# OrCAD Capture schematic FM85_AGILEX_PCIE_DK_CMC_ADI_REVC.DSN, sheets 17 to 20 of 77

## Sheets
17 FPGA BANK 2C: size B
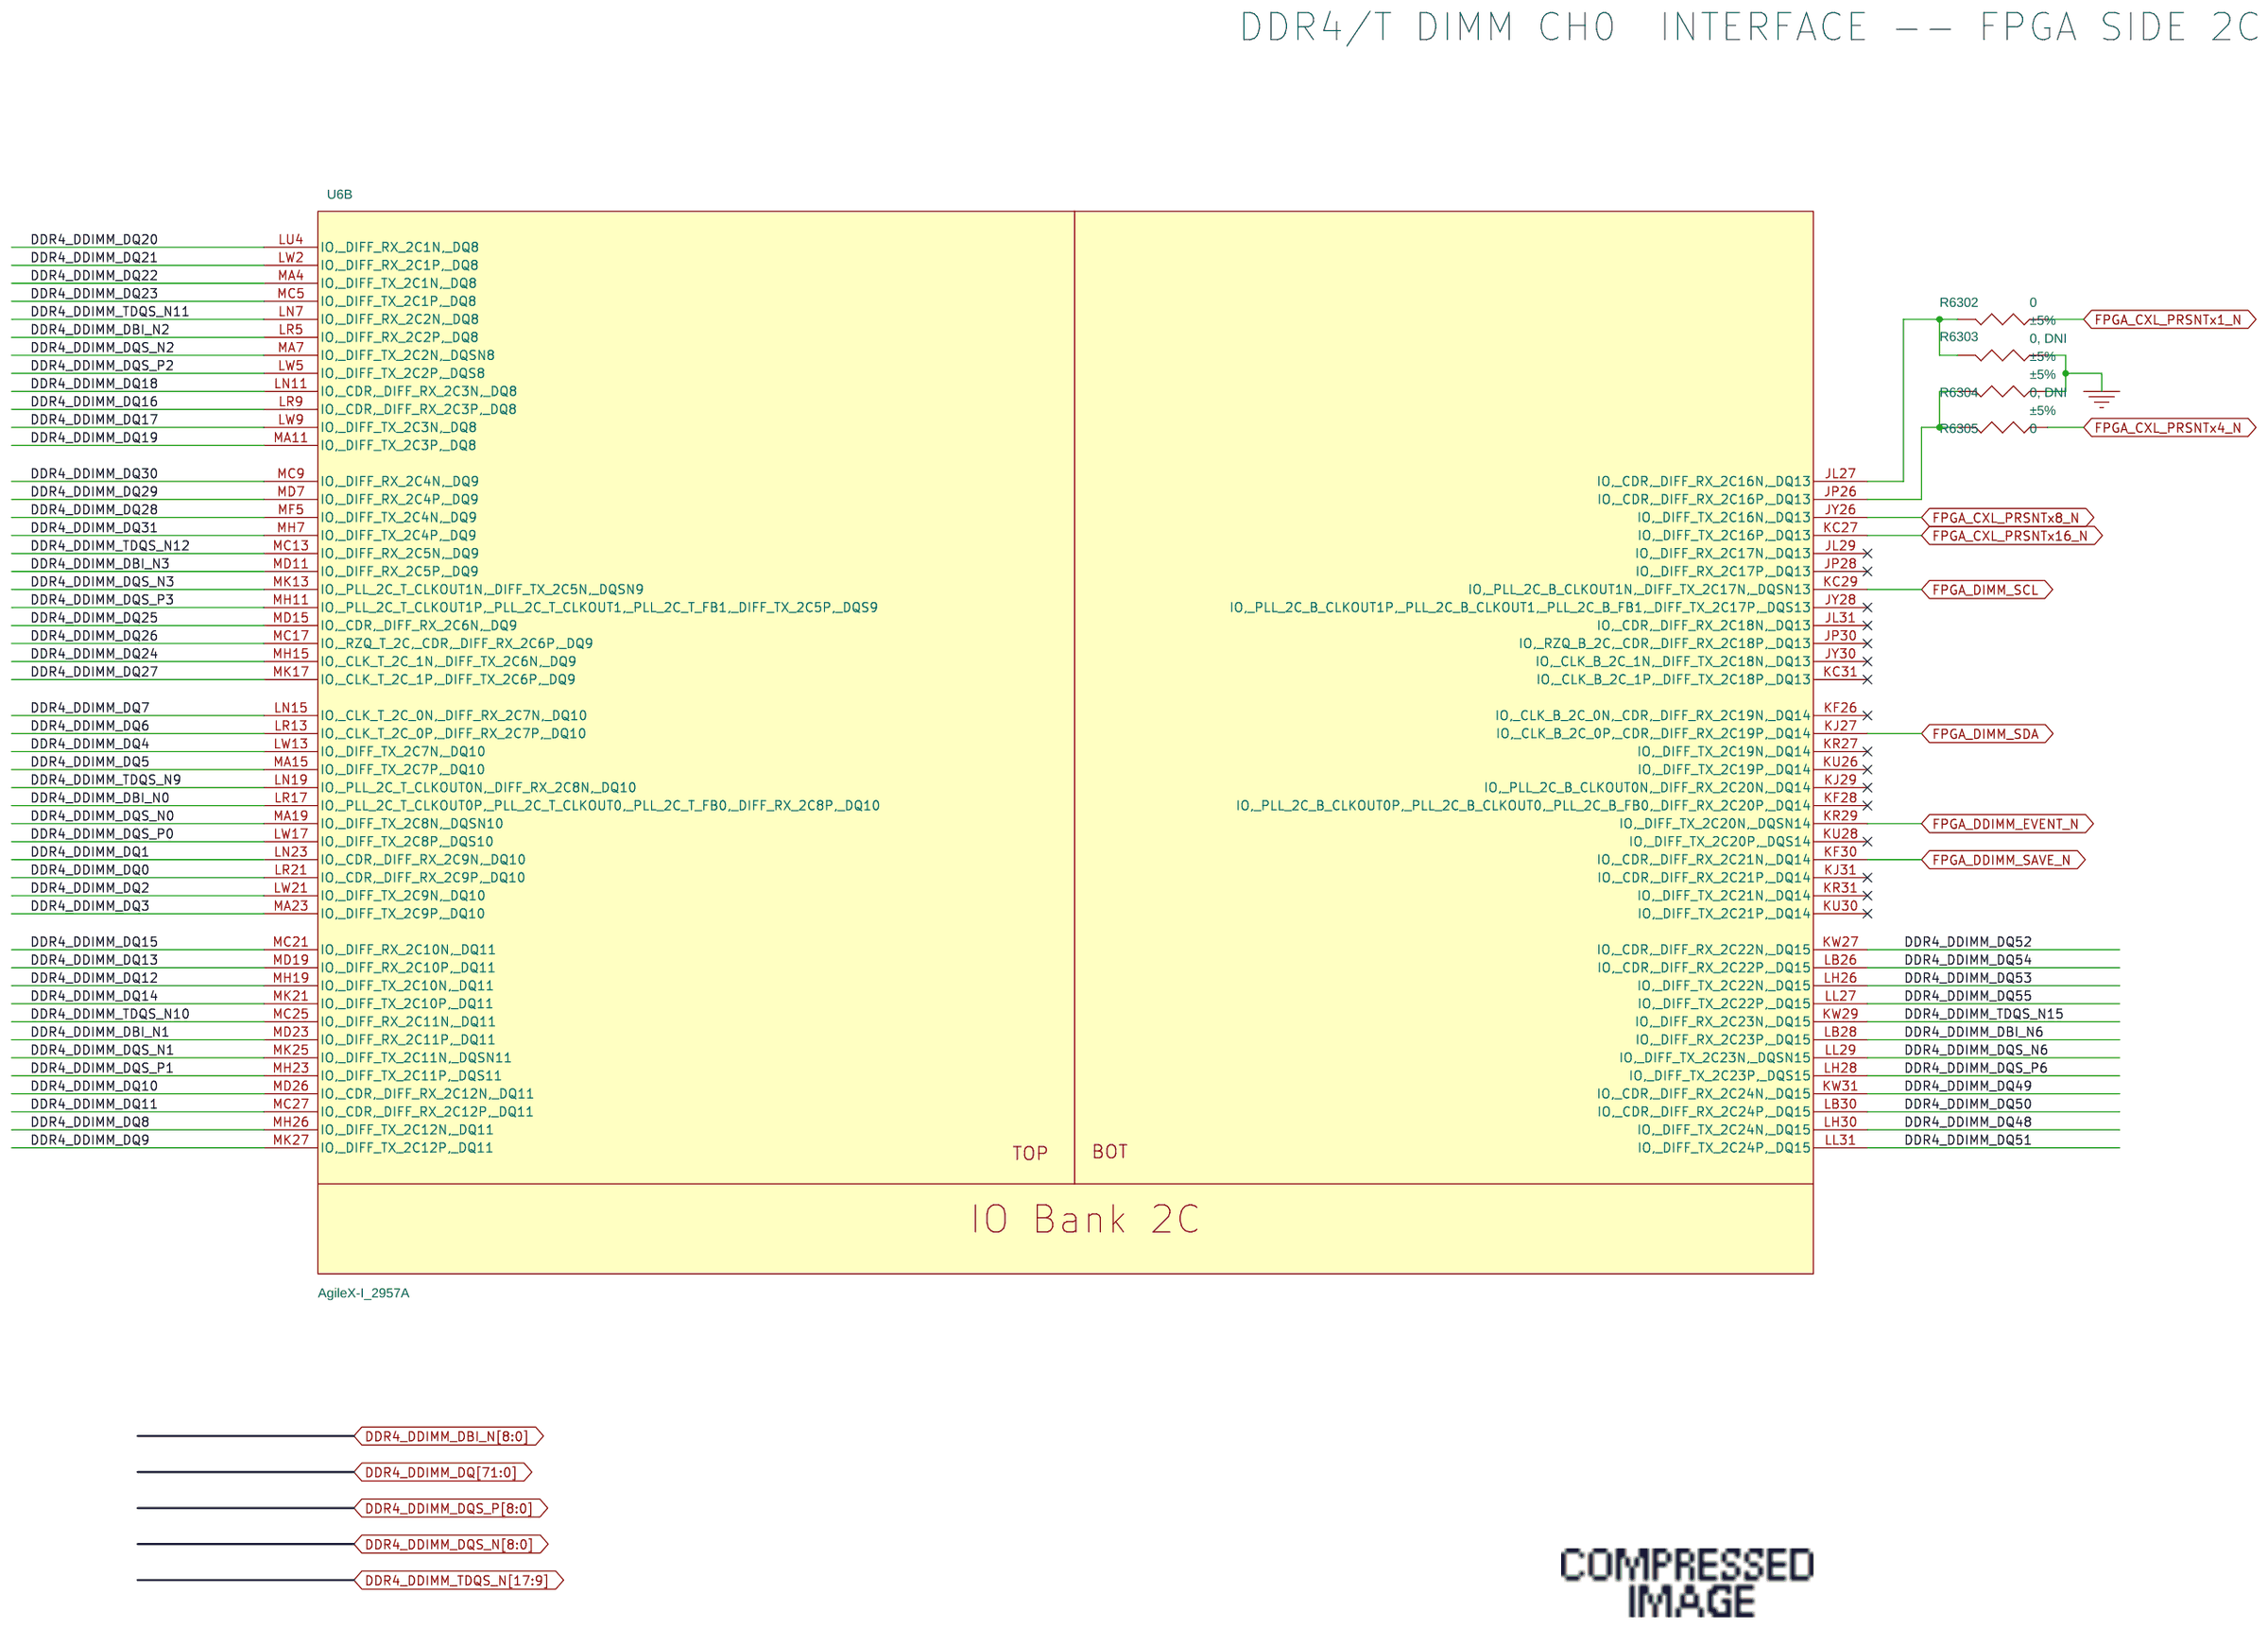
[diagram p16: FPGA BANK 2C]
18 FPGA BANK 2F: size B
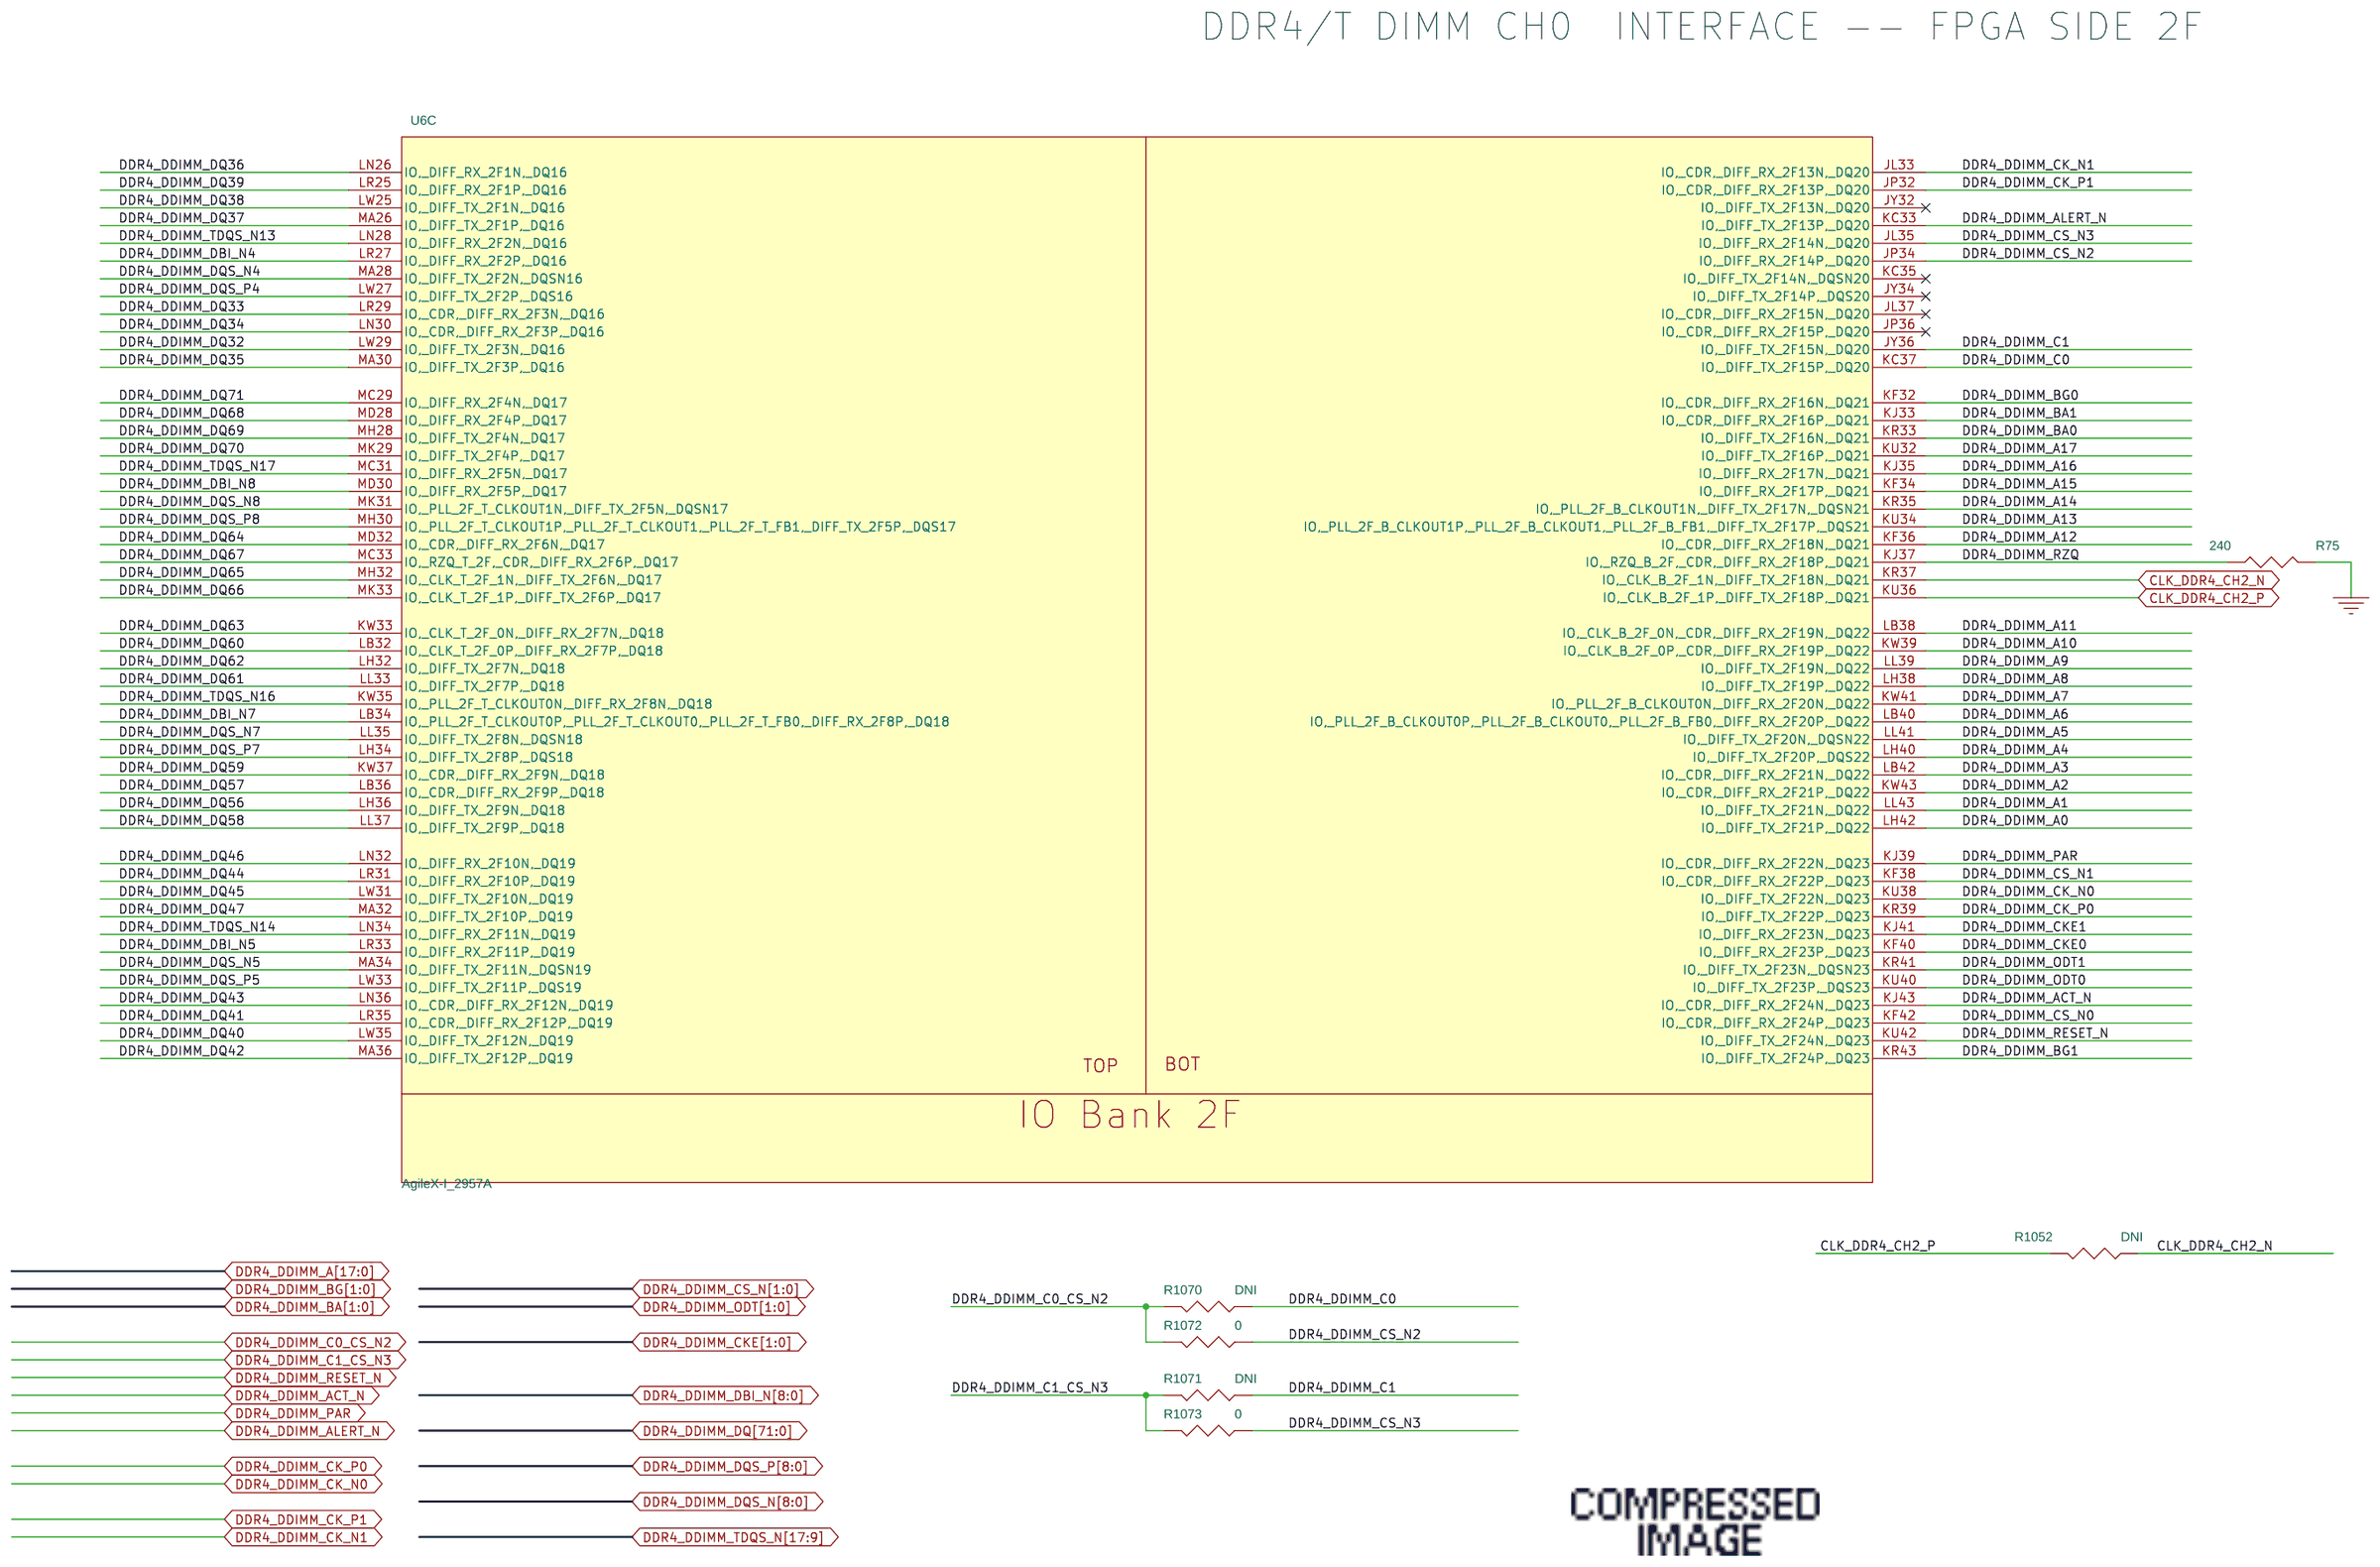
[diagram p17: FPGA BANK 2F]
19 DDR4/DDRT DIMM2: size B
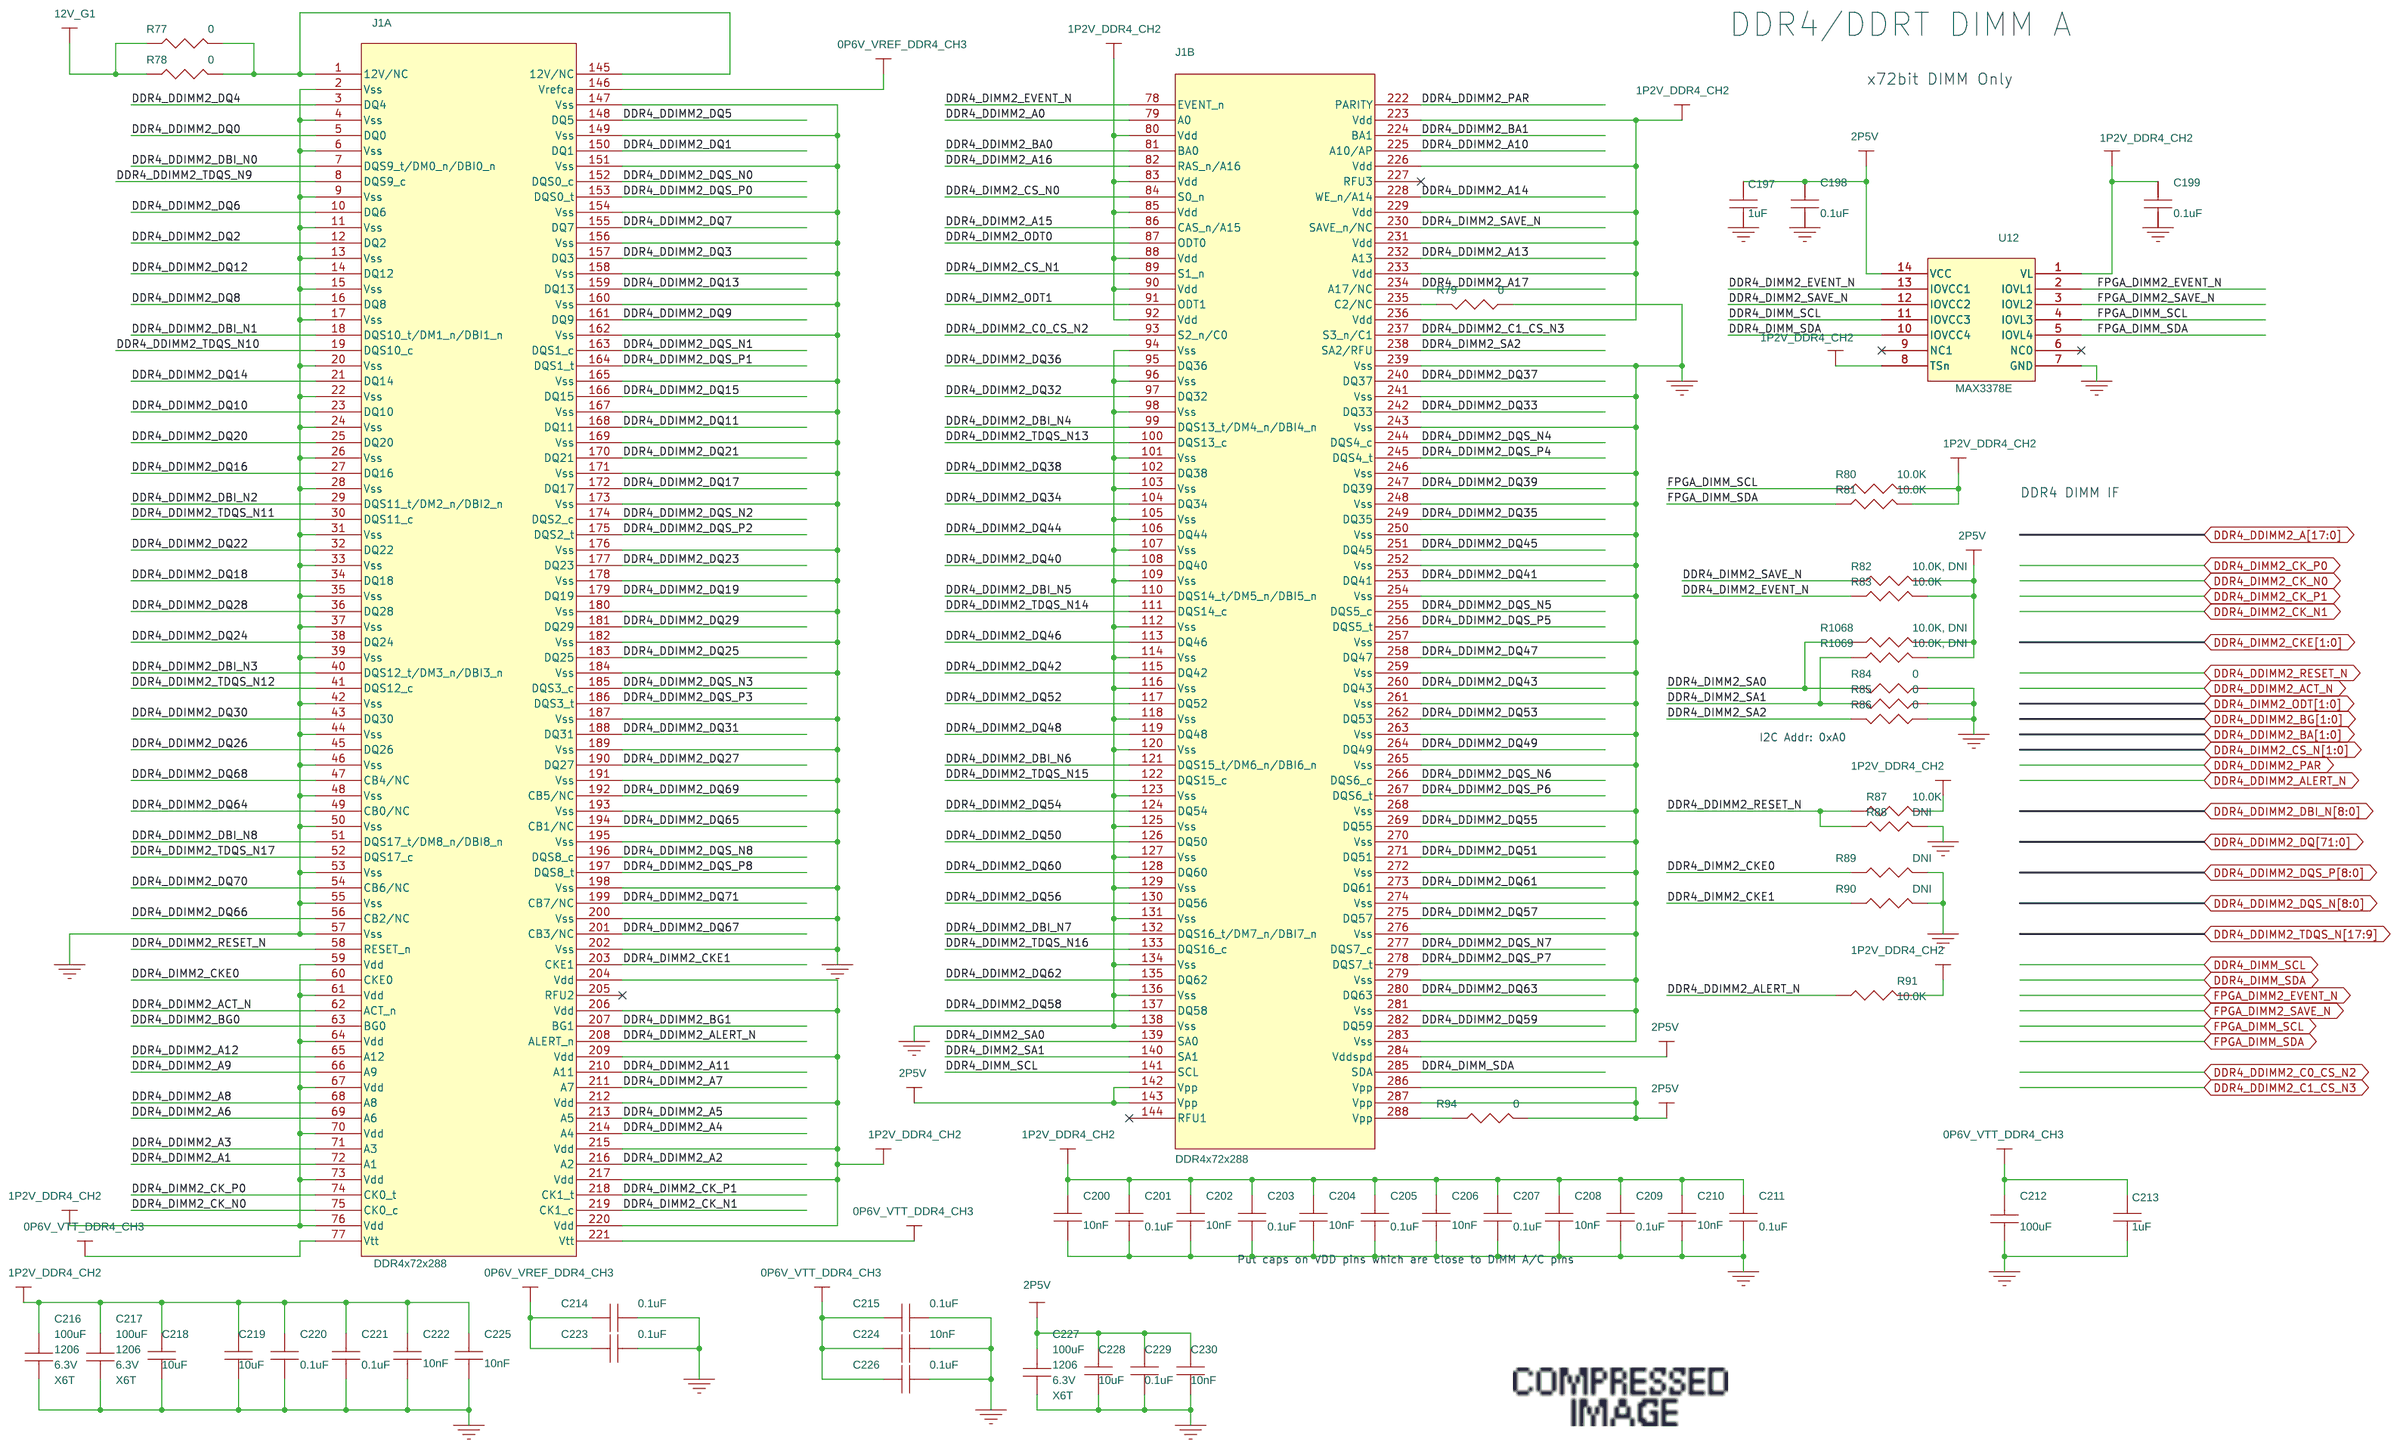
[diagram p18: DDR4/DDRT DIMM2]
20 DDR4/DDRT DIMM: size B
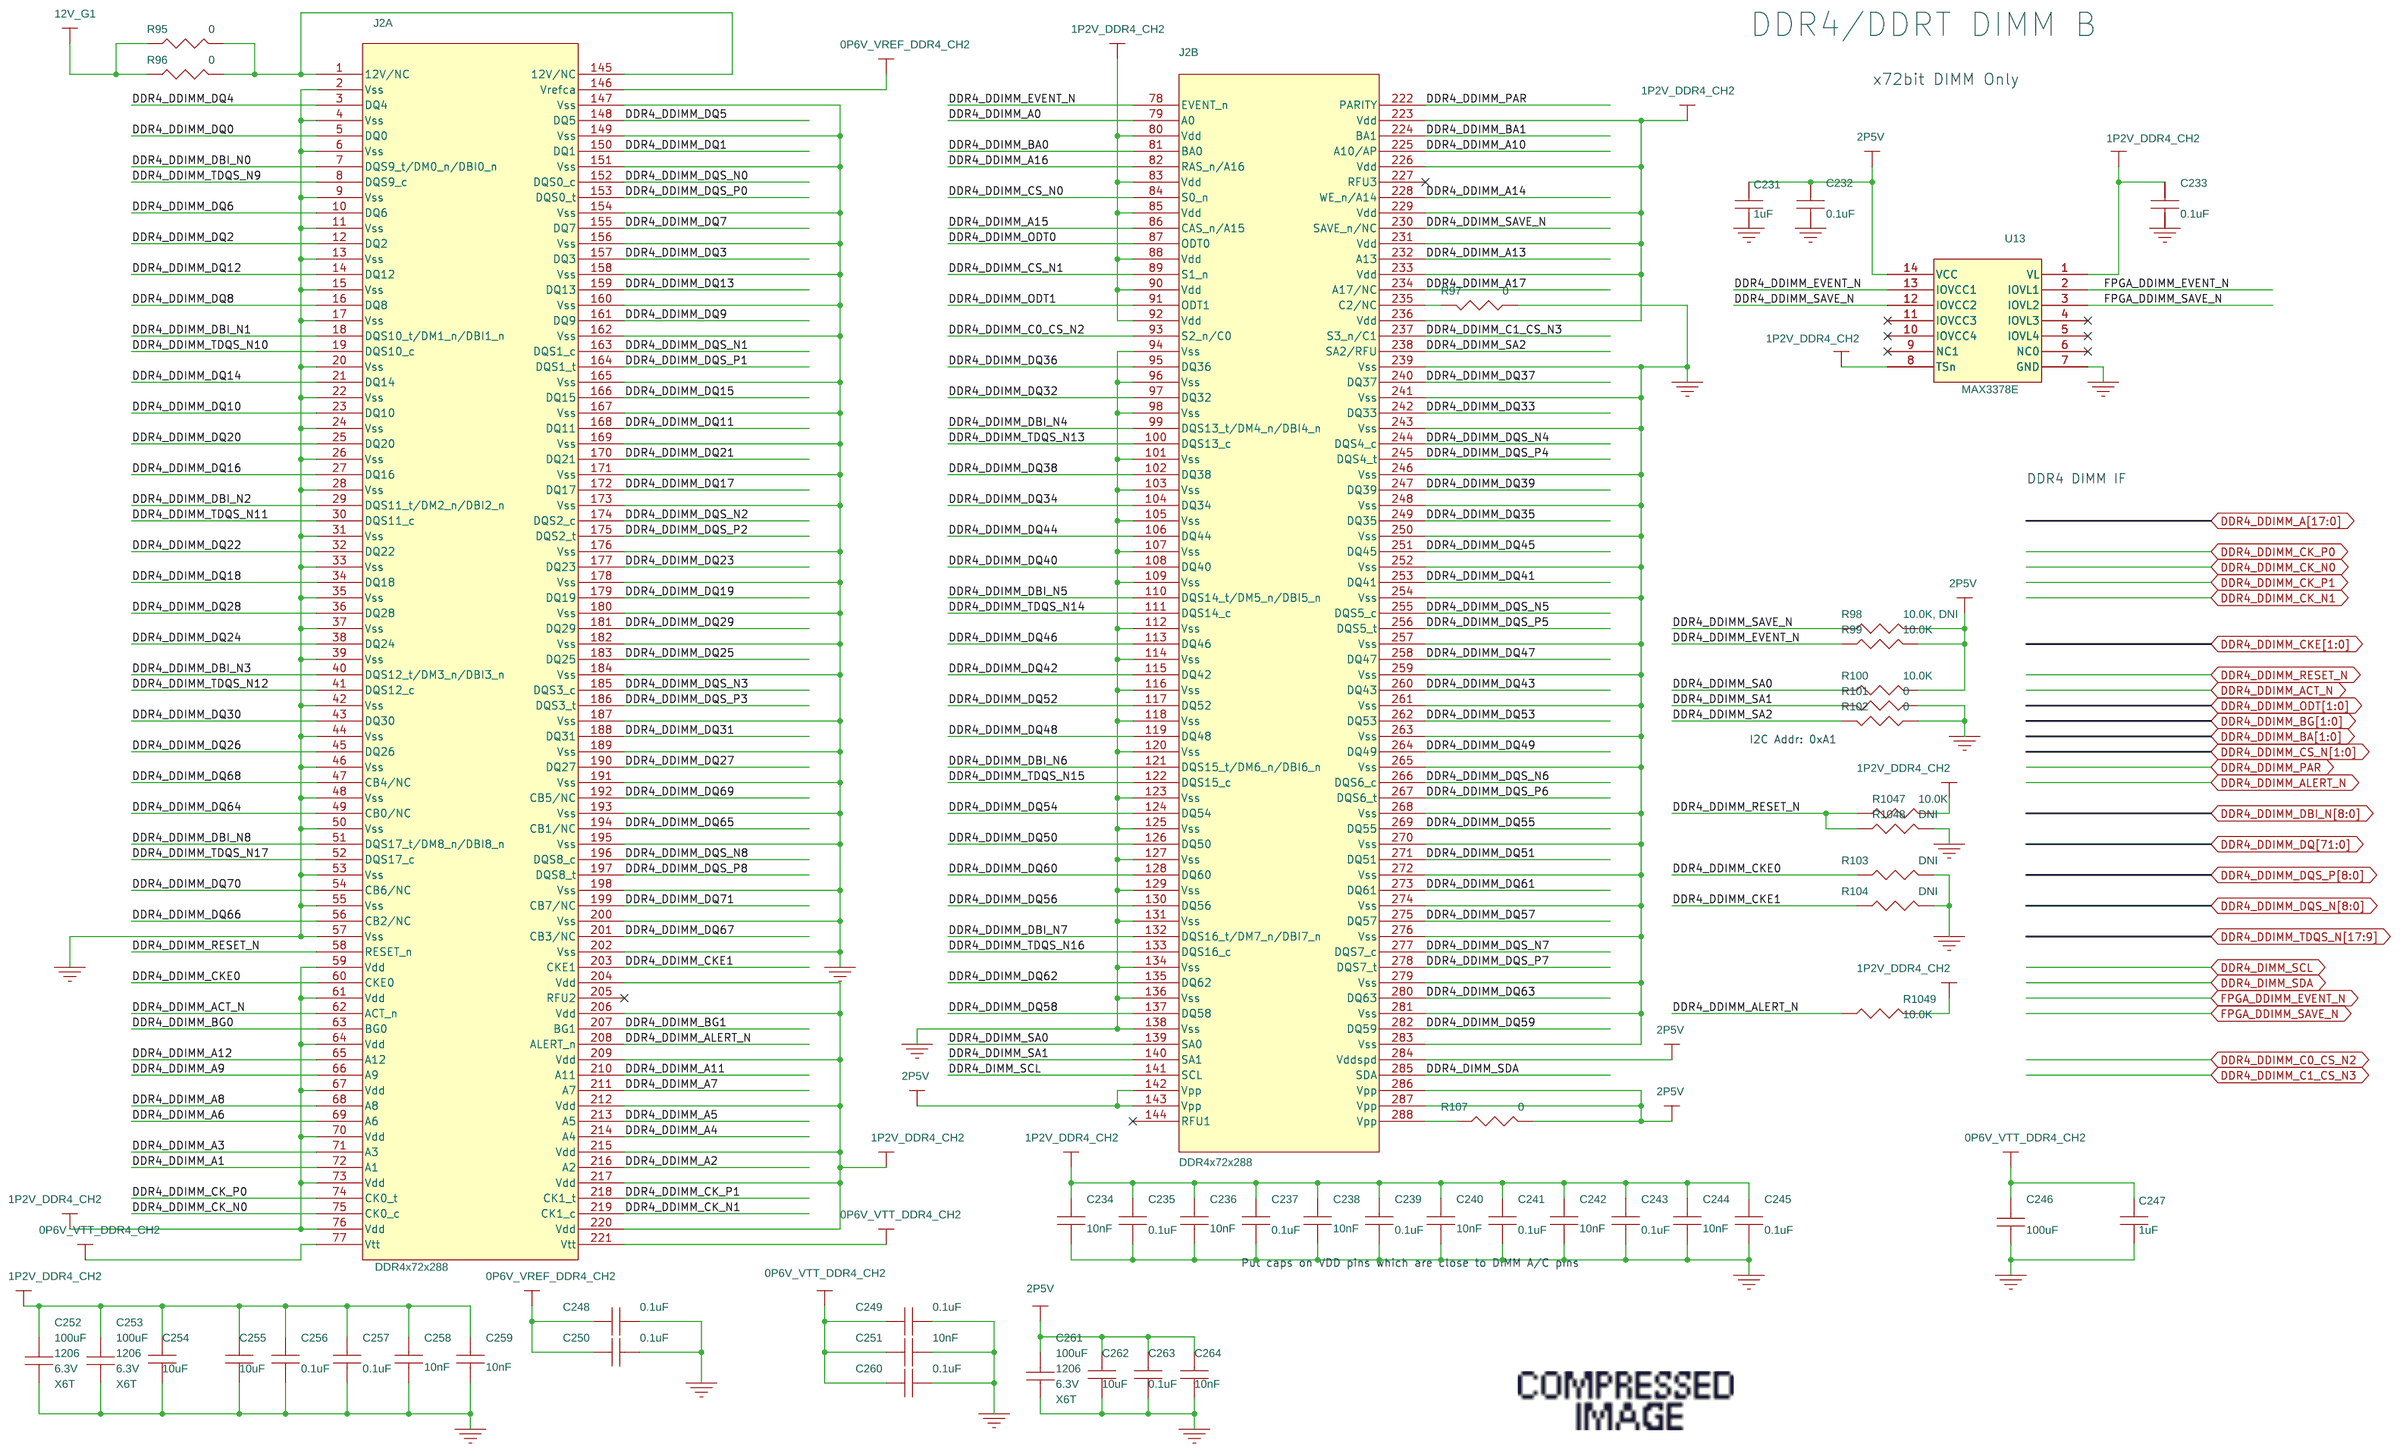
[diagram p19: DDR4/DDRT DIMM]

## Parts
sheet DDR4/DDRT DIMM2
C197  1uF  [0402]
C198  0.1uF  [0402]
C199  0.1uF  [0402]
C200  10nF  [0402]
C201  0.1uF  [0402]
C202  10nF  [0402]
C203  0.1uF  [0402]
C204  10nF  [0402]
C205  0.1uF  [0402]
C206  10nF  [0402]
C207  0.1uF  [0402]
C208  10nF  [0402]
C209  0.1uF  [0402]
C210  10nF  [0402]
C211  0.1uF  [0402]
C212  100uF  [1206]
C213  1uF  [0402]
C214  0.1uF  [0402]
C215  0.1uF  [0402]
C216  100uF  [1206]
C217  100uF  [1206]
C218  10uF  [1210]
C219  10uF  [1210]
C220  0.1uF  [0402]
C221  0.1uF  [0402]
C222  10nF  [0402]
C223  0.1uF  [0402]
C224  10nF  [0402]
C225  10nF  [0402]
C226  0.1uF  [0402]
C227  100uF  [1206]
C228  10uF  [1210]
C229  0.1uF  [0402]
C230  10nF  [0402]
J1  DDR4x72x288  [DDR4DIMM_SMT]  (sections A,B)
R77  0  [1206]
R78  0  [1206]
R79  0  [0402]
R80  10.0K  [0402]
R81  10.0K  [0402]
R82  10.0K, DNI  [0402]
R83  10.0K  [0402]
R84  0  [0402]
R85  0  [0402]
R86  0  [0402]
R87  10.0K  [0402]
R88  DNI  [0402]
R89  DNI  [0402]
R90  DNI  [0402]
R91  10.0K  [0402]
R94  0  [0603]
R1068  10.0K, DNI  [0402]
R1069  10.0K, DNI  [0402]
U12  MAX3378E  [TSSOP-14]
sheet DDR4/DDRT DIMM
C231  1uF  [0402]
C232  0.1uF  [0402]
C233  0.1uF  [0402]
C234  10nF  [0402]
C235  0.1uF  [0402]
C236  10nF  [0402]
C237  0.1uF  [0402]
C238  10nF  [0402]
C239  0.1uF  [0402]
C240  10nF  [0402]
C241  0.1uF  [0402]
C242  10nF  [0402]
C243  0.1uF  [0402]
C244  10nF  [0402]
C245  0.1uF  [0402]
C246  100uF  [1206]
C247  1uF  [0402]
C248  0.1uF  [0402]
C249  0.1uF  [0402]
C250  0.1uF  [0402]
C251  10nF  [0402]
C252  100uF  [1206]
C253  100uF  [1206]
C254  10uF  [1210]
C255  10uF  [1210]
C256  0.1uF  [0402]
C257  0.1uF  [0402]
C258  10nF  [0402]
C259  10nF  [0402]
C260  0.1uF  [0402]
C261  100uF  [1206]
C262  10uF  [1210]
C263  0.1uF  [0402]
C264  10nF  [0402]
J2  DDR4x72x288  [DDR4DIMM_SMT]  (sections A,B)
R95  0  [1206]
R96  0  [1206]
R97  0  [0402]
R98  10.0K, DNI  [0402]
R99  10.0K  [0402]
R100  10.0K  [0402]
R101  0  [0402]
R102  0  [0402]
R103  DNI  [0402]
R104  DNI  [0402]
R107  0  [0603]
R1047  10.0K  [0402]
R1048  DNI  [0402]
R1049  10.0K  [0402]
U13  MAX3378E  [TSSOP-14]
sheet FPGA BANK 2C
R6302  0  [0402]
R6303  0, DNI  [0402]
R6304  0, DNI  [0402]
R6305  0  [0402]
sheet FPGA BANK 2F
R75  240  [0402]
R1052  DNI  [0402]
R1070  DNI  [0402]
R1071  DNI  [0402]
R1072  0  [0402]
R1073  0  [0402]
U6  AgileX-I_2957A  [fbga2957a_hex_p56x45]  (sections A,B,C,D,E,F,G,H,I,J,K,L,M,N,O,P,Q,R,S,T,U,V,W,X,Y,Z)

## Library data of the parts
C197 C213 C231 C247 = CAP: CAP - CER, 1uF, 10V, +/-10%, X5R, 0402; Item Num: G61001-001; Lead Free Status: Yes; Manufacturer: Murata; Manufacturer Part Num: GRM155R61A105KE15D; Num Pins: 2; Part Class: CAPACITORS; RoHS Compliant: Yes
C198 C199 C201 C203 C205 C207 C211 C214 C215 C220 C221 C223 C226 C229 C232 C233 C241 C245 C248-C250 C256 C257 C263 = CAP: CAPC,  X7R, 0402, 0.1uF, 25V, ±20%; Item Num: K13660-001; LIFECYCLE_PHASE: Active; Lead Free Status: Lead Free; MFR_LIFECYCLE: Active; Manufacturer: Murata; Manufacturer Part Num: GRM155R71E104KE14D; Num Pins: 2; PART_SUBCLASS: CAPACITORS; Part Class: CAPACITORS; RATED_VOLTAGE: 25V; RoHS Compliant: RoHS Compliant; Tolerance: +80%/-20%
C200 C202 C204 C206 C208 C210 C222 C224 C225 C230 C234 C236 C238 C240 C242 C244 C251 C258 C259 C264 = Cap_10000PF_50V_0402: CAP - CERAMIC, 10nF, 0402, 50V, Y5V; Item Num: K30697-001; Manufacturer Part Num: GRM155F51H103Z
C209 C243 = CAP: CAPC,  X7R, 0402, 0.1uF, 25V, ±20%; Dielectric: Y5V; Item Num: K13660-001; LIFECYCLE_PHASE: Active; Lead Free Status: Lead Free; MFR_LIFECYCLE: Active; Manufacturer: Murata; Manufacturer Part Num: GRM155R71E104KE14D; Num Pins: 2; PART_SUBCLASS: CAPACITORS; Part Class: CAPACITORS; RATED_VOLTAGE: 25V; RoHS Compliant: RoHS Compliant; Tolerance: +80%/-20%
C212 C216 C217 C227 C246 C252 C253 C261 = CAP: CAP CER 100UF 6.3V X6T 1206; AGILE_LINK: http://sj-agile9app/Agile/PLMServlet?action=OpenEmailObject&classid=10000&objid=257560276; Item Num: H65271-004; LIFECYCLE_PHASE: Active; Lead Free Status: Lead Free; MFR_LIFECYCLE: Active; Manufacturer: Murata; Manufacturer Part Num: GRM31CD80J107ME39L; Num Pins: 2; PART_SUBCLASS: CAPACITORS; RATED_VOLTAGE: 6.3V; RoHS Compliant: RoHS Compliant; TOLERANCE: 20%; Temperature Coefficient: X6T
C218 = CAP_10uF_+_-10%_25V_1210: CAP - CER, 10UF, 25V, 10%, X5R, 1210; Agile Part Description: CAP - CER, 10UF, 25V, 10%, X5R, 1210; Item Num: G19458-001; Manufacturer Part Num: GRM32DR61E106KA12L
C219 C254 C255 = CAP_10uF_+_-10%_25V_1210: CAP - CER, 10UF, 25V, 10%, X5R, 1210; Agile Part Description: CAP - CER, 10UF, 25V, 10%, X7R, 1210; Item Num: G19458-001; Manufacturer Part Num: GRM32DR61E106KA12L
C228 C262 = CAP_10uF_+_-10%_25V_1210: CAP - CER, 10UF, 25V, 10%, X7R, 1210; Agile Part Description: CAP - CER, 10UF, 25V, 10%, X5R, 1210; Item Num: G19458-001; Manufacturer Part Num: GRM32DR61E106KA12L
J1 J2 = DDR4x72x288_1: CONN SMT DDR4 288POS VERT; COMPGROUP: DDR4_PINGPONG_DIMMA; Item Num: K21528-001; Manufacturer: Molex Inc; Manufacturer Part Num: 787301002
R77 R78 R95 R96 = RESISTOR: RES SMD 0 OHM JUMPER 3/4W 1206; AGILE_LINK: http://sj-agile9app/Agile/PLMServlet?action=OpenEmailObject&classid=10000&objid=146548997; Item Num: A93552-015; LIFECYCLE_PHASE: Active; Lead Free Status: No; MFR_LIFECYCLE: Active; Manufacturer: Vishay Dale; Manufacturer Part Num: CRCW12060000Z0EAHP; Num Pins: 2; PART_SUBCLASS: RESISTORS; POWER: 3/4W; RoHS Compliant: Yes; TOLERANCE: +/-1%
R79 R84-R86 R97 R101 R102 R1070-R1073 = RES_0_OHM_5%_1_16W_0402_SMD: Item Num: H30887-001
R80 R81 R83 R87 R91 R99 R100 R1047 R1049 = RESISTOR: RES,10.0K OHMS,1.0%,1/16W, 0402; AGILE_LINK: http://sj-agile9app/Agile/PLMServlet?action=OpenEmailObject&classid=10000&objid=146548997; Item Num: K28115-001; LIFECYCLE_PHASE: Active; Lead Free Status: No; MFR_LIFECYCLE: Active; Manufacturer: Panasonic; Manufacturer Part Num: ERJ-2RKF1002X; Num Pins: 2; PART_SUBCLASS: RESISTORS; POWER: 1/16W; RoHS Compliant: Yes; TOLERANCE: +/-1%
R82 R98 R1068 R1069 = RESISTOR: RES,10.0K OHMS,1.0%,1/16W, 0402; AGILE_LINK: http://sj-agile9app/Agile/PLMServlet?action=OpenEmailObject&classid=10000&objid=146548997; Item Num: K28115-001; LIFECYCLE_PHASE: Active; Lead Free Status: No; MFR_LIFECYCLE: Active; Manufacturer: Panasonic; Manufacturer Part Num: ERJ-2RKF1002X; Num Pins: 2; PART_SUBCLASS: RESISTORS; POWER: 1/16W; RESISTANCE: 10.0K; RoHS Compliant: Yes; TOLERANCE: +/-1%
R88-R90 R103 R104 R1048 = RESISTOR: RES ZERO OHM 1/16W 5% 0402 SMD; Item Num: H30887-001; Lead Free Status: No; Manufacturer: Panasonic; Manufacturer Part Num: ERJ-2GE0R00X; Num Pins: 2; Part Class: RESISTORS; Price: 0; RoHS Compliant: Yes; Tolerance: 5%
R94 R107 = RESISTOR: RES - 0 OHM, 5% 0603 1/10W; Item Num: E57868-001; Lead Free Status: No; Manufacturer: Panasonic; Manufacturer Part Num: ERJ-3GEY0R00V; Num Pins: 2; Part Class: RESISTORS; RoHS Compliant: Yes; Tolerance: 5%
U12 U13 = MAX3378E_0: IC - QUAD LOW-VOLTAGE LEVEL TRANSLATOR, +/- 15KV, ESD-PROTECTED, 1UA, 16MBPS; Item Num: C34337-001; Manufacturer: Maxim; Manufacturer Part Num: MAX3378EEUD
C235 = CAP: CAPC,  X7R, 0402, 0.1uF, 25V, ±20%; Dielectric: X7R; Item Num: K13660-001; LIFECYCLE_PHASE: Active; Lead Free Status: Lead Free; MFR_LIFECYCLE: Active; Manufacturer: Murata; Manufacturer Part Num: GRM155R71E104KE14D; Num Pins: 2; PART_SUBCLASS: CAPACITORS; Part Class: CAPACITORS; RATED_VOLTAGE: 25V; RoHS Compliant: RoHS Compliant; Tolerance: +80%/-20%
C237 C260 = CAP: CAPC,  X7R, 0402, 0.1uF, 25V, ±20%; Item Num: K13660-001; LIFECYCLE_PHASE: Active; Lead Free Status: Lead Free; MFR_LIFECYCLE: Active; Manufacturer: Murata; Manufacturer Part Num: GRM155F51E104ZA01D; Num Pins: 2; PART_SUBCLASS: CAPACITORS; Part Class: CAPACITORS; RATED_VOLTAGE: 25V; RoHS Compliant: RoHS Compliant; Tolerance: +80%/-20%
C239 = CAP: CAP - CERAMIC,  0.1UF 0402 25VDC X7R; Dielectric: Y5V; Item Num: K13560-001; LIFECYCLE_PHASE: Active; Lead Free Status: Lead Free; MFR_LIFECYCLE: Active; Manufacturer: Murata; Manufacturer Part Num: GRM155R71E104KE14D; Num Pins: 2; PART_SUBCLASS: CAPACITORS; Part Class: CAPACITORS; RATED_VOLTAGE: 25V; RoHS Compliant: RoHS Compliant; Tolerance: +80%/-20%
R6302 R6305 = RESISTOR: RES ZERO OHM 1/16W 5% 0402 SMD; Agile IPN: P02-14020R; Altera Part No.: P02-14020R; Item Num: H30887-001; Lead Free Status: No; Manufacturer: Panasonic; Manufacturer Part Num: ERJ-2GE0R00X; Num Pins: 2; Part Class: RESISTORS; RoHS Compliant: Yes; Tolerance: ±5%
R6303 R6304 = RESISTOR: RES ZERO OHM 1/16W 5% 0402 SMD; Agile IPN: P02-14020R; Altera Part No.: P02-14020R; Item Num: H30887-001; Lead Free Status: No; Manufacturer: Panasonic; Manufacturer Part Num: ERJ-2GE0R00X; Num Pins: 2; Part Class: RESISTORS; Price: 0; RoHS Compliant: Yes; Tolerance: ±5%
R75 = RESISTOR: RES - 240 OHM, 1/16W, 1%, 0402 SMD; Item Num: K15783-001; LIFECYCLE_PHASE: Active; Lead Free Status: Lead Free; MFR_LIFECYCLE: Active; Manufacturer: Panasonic; Manufacturer Part Num: ERJ-2RKF2400X; Num Pins: 2; PART_SUBCLASS: RESISTORS; RoHS Compliant: RoHS Compliant
R1052 = RESISTOR: RES,100 OHMS,1.0%,1/16W,0402; Item Num: A36092-043; Lead Free Status: No; Manufacturer: Panasonic; Manufacturer Part Num: ERJ-2RKF1000X; Manufacturer's Part No.: ERJ-2RKF1000X; Num Pins: 2; Part Class: RESISTORS; Price: 0; RoHS Compliant: Yes
U6 = AgileX-I_2957A: Item Num: 99C7VA

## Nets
12V_G1: R77.1 R78.1 R95.1 R96.1 ; also on sheet 50 53 54 55 56
GND: C197.2 C198.2 C199.2 C200.2 C201.2 C202.2 C203.2 C204.2 C205.2 C206.2 C207.2 C208.2 C209.2 C210.2 C211.2 C212.1 C213.2 C214.2 C215.2 C216.1 C217.1 C218.2 C219.2 C220.2 C221.2 C222.2 C223.2 C224.2 C225.2 C226.2 C227.1 C228.2 C229.2 C230.2 C231.2 C232.2 C233.2 C234.2 C235.2 C236.2 C237.2 C238.2 C239.2 C240.2 C241.2 C242.2 C243.2 C244.2 C245.2 C246.1 C247.2 C248.2 C249.2 C250.2 C251.2 C252.1 C253.1 C254.2 C255.2 C256.2 C257.2 C258.2 C259.2 C260.2 C261.1 C262.2 C263.2 C264.2 J1.2(Vss) J1.4(Vss) J1.6(Vss) J1.9(Vss) J1.11(Vss) J1.13(Vss) J1.15(Vss) J1.17(Vss) J1.20(Vss) J1.22(Vss) J1.24(Vss) J1.26(Vss) J1.28(Vss) J1.31(Vss) J1.33(Vss) J1.35(Vss) J1.37(Vss) J1.39(Vss) J1.42(Vss) J1.44(Vss) J1.46(Vss) J1.48(Vss) J1.50(Vss) J1.53(Vss) J1.55(Vss) J1.57(Vss) J1.94(Vss) J1.96(Vss) J1.98(Vss) J1.101(Vss) J1.103(Vss) J1.105(Vss) J1.107(Vss) J1.109(Vss) J1.112(Vss) J1.114(Vss) J1.116(Vss) J1.118(Vss) J1.120(Vss) J1.123(Vss) J1.125(Vss) J1.127(Vss) J1.129(Vss) J1.131(Vss) J1.134(Vss) J1.136(Vss) J1.138(Vss) J1.147(Vss) J1.149(Vss) J1.151(Vss) J1.154(Vss) J1.156(Vss) J1.158(Vss) J1.160(Vss) J1.162(Vss) J1.165(Vss) J1.167(Vss) J1.169(Vss) J1.171(Vss) J1.173(Vss) J1.176(Vss) J1.178(Vss) J1.180(Vss) J1.182(Vss) J1.184(Vss) J1.187(Vss) J1.189(Vss) J1.191(Vss) J1.193(Vss) J1.195(Vss) J1.198(Vss) J1.200(Vss) J1.202(Vss) J1.239(Vss) J1.241(Vss) J1.243(Vss) J1.246(Vss) J1.248(Vss) J1.250(Vss) J1.252(Vss) J1.254(Vss) J1.257(Vss) J1.259(Vss) J1.261(Vss) J1.263(Vss) J1.265(Vss) J1.268(Vss) J1.270(Vss) J1.272(Vss) J1.274(Vss) J1.276(Vss) J1.279(Vss) J1.281(Vss) J1.283(Vss) J2.2(Vss) J2.4(Vss) J2.6(Vss) J2.9(Vss) J2.11(Vss) J2.13(Vss) J2.15(Vss) J2.17(Vss) J2.20(Vss) J2.22(Vss) J2.24(Vss) J2.26(Vss) J2.28(Vss) J2.31(Vss) J2.33(Vss) J2.35(Vss) J2.37(Vss) J2.39(Vss) J2.42(Vss) J2.44(Vss) J2.46(Vss) J2.48(Vss) J2.50(Vss) J2.53(Vss) J2.55(Vss) J2.57(Vss) J2.94(Vss) J2.96(Vss) J2.98(Vss) J2.101(Vss) J2.103(Vss) J2.105(Vss) J2.107(Vss) J2.109(Vss) J2.112(Vss) J2.114(Vss) J2.116(Vss) J2.118(Vss) J2.120(Vss) J2.123(Vss) J2.125(Vss) J2.127(Vss) J2.129(Vss) J2.131(Vss) J2.134(Vss) J2.136(Vss) J2.138(Vss) J2.147(Vss) J2.149(Vss) J2.151(Vss) J2.154(Vss) J2.156(Vss) J2.158(Vss) J2.160(Vss) J2.162(Vss) J2.165(Vss) J2.167(Vss) J2.169(Vss) J2.171(Vss) J2.173(Vss) J2.176(Vss) J2.178(Vss) J2.180(Vss) J2.182(Vss) J2.184(Vss) J2.187(Vss) J2.189(Vss) J2.191(Vss) J2.193(Vss) J2.195(Vss) J2.198(Vss) J2.200(Vss) J2.202(Vss) J2.239(Vss) J2.241(Vss) J2.243(Vss) J2.246(Vss) J2.248(Vss) J2.250(Vss) J2.252(Vss) J2.254(Vss) J2.257(Vss) J2.259(Vss) J2.261(Vss) J2.263(Vss) J2.265(Vss) J2.268(Vss) J2.270(Vss) J2.272(Vss) J2.274(Vss) J2.276(Vss) J2.279(Vss) J2.281(Vss) J2.283(Vss) R75.2 R79.1 R84.1 R85.1 R86.1 R88.1 R89.1 R90.1 R97.1 R101.1 R102.1 R103.1 R104.1 R1048.1 R6303.2 R6304.2 U12.7(GND) U13.7(GND) ; also on sheet 9 10 11 13 14 15 16 21 22 23 25 26 27 28 29 30 31 32 33 34 35 36 38 39 40 41 42 43 44 45 46 47 48 49 50 51 52 53 54 55 56 57 58 59 60 61 62 63 64 65 66 67 68 69 70 71 72 73 74 75 76 77
0p6V_VREF_DDR4_CH2: C248.1 C250.1 J2.146(Vrefca) ; also on sheet 39 72 76
0p6V_VREF_DDR4_CH3: C214.1 C223.1 J1.146(Vrefca) ; also on sheet 39 72 76
0p6V_VTT_DDR4_CH2: C246.2 C247.1 C249.1 C251.1 C260.1 J2.77(Vtt) J2.221(Vtt) ; also on sheet 72
0p6V_VTT_DDR4_CH3: C212.2 C213.1 C215.1 C224.1 C226.1 J1.77(Vtt) J1.221(Vtt) ; also on sheet 72
1p2V_DDR4_CH2: C199.1 C200.1 C201.1 C202.1 C203.1 C204.1 C205.1 C206.1 C207.1 C208.1 C209.1 C210.1 C211.1 C216.2 C217.2 C218.1 C219.1 C220.1 C221.1 C222.1 C225.1 C233.1 C234.1 C235.1 C236.1 C237.1 C238.1 C239.1 C240.1 C241.1 C242.1 C243.1 C244.1 C245.1 C252.2 C253.2 C254.1 C255.1 C256.1 C257.1 C258.1 C259.1 J1.59(Vdd) J1.61(Vdd) J1.64(Vdd) J1.67(Vdd) J1.70(Vdd) J1.73(Vdd) J1.76(Vdd) J1.80(Vdd) J1.83(Vdd) J1.85(Vdd) J1.88(Vdd) J1.90(Vdd) J1.92(Vdd) J1.204(Vdd) J1.206(Vdd) J1.209(Vdd) J1.212(Vdd) J1.215(Vdd) J1.217(Vdd) J1.220(Vdd) J1.223(Vdd) J1.226(Vdd) J1.229(Vdd) J1.231(Vdd) J1.233(Vdd) J1.236(Vdd) J2.59(Vdd) J2.61(Vdd) J2.64(Vdd) J2.67(Vdd) J2.70(Vdd) J2.73(Vdd) J2.76(Vdd) J2.80(Vdd) J2.83(Vdd) J2.85(Vdd) J2.88(Vdd) J2.90(Vdd) J2.92(Vdd) J2.204(Vdd) J2.206(Vdd) J2.209(Vdd) J2.212(Vdd) J2.215(Vdd) J2.217(Vdd) J2.220(Vdd) J2.223(Vdd) J2.226(Vdd) J2.229(Vdd) J2.231(Vdd) J2.233(Vdd) J2.236(Vdd) R80.2 R81.2 R87.2 R91.2 R1047.2 R1049.2 U12.1(VL) U12.8(TSn) U13.1(VL) U13.8(TSn) ; also on sheet 30 39 71 72 76
2p5V: C197.1 C198.1 C227.2 C228.1 C229.1 C230.1 C231.1 C232.1 C261.2 C262.1 C263.1 C264.1 J1.142(Vpp) J1.143(Vpp) J1.284(Vddspd) J1.286(Vpp) J1.287(Vpp) J2.142(Vpp) J2.143(Vpp) J2.284(Vddspd) J2.286(Vpp) J2.287(Vpp) R82.2 R83.2 R94.1 R98.2 R99.2 R100.2 R107.1 R1068.2 R1069.2 U12.14(VCC) U13.14(VCC) ; also on sheet 9 10 11 14 15 16 43 45 46 73
CLK_DDR4_CH2_N: R1052.1 U6.KR37(IO,_CLK_B_2F_1N,_DIFF_TX_2F18N,_DQ21) ; also on sheet 43
CLK_DDR4_CH2_P: R1052.2 U6.KU36(IO,_CLK_B_2F_1P,_DIFF_TX_2F18P,_DQ21) ; also on sheet 43
DDR4_DDIMM2_A0: J1.79(A0) ; also on sheet 13
DDR4_DDIMM2_A1: J1.72(A1) ; also on sheet 13
DDR4_DDIMM2_A2: J1.216(A2) ; also on sheet 13
DDR4_DDIMM2_A3: J1.71(A3) ; also on sheet 13
DDR4_DDIMM2_A4: J1.214(A4) ; also on sheet 13
DDR4_DDIMM2_A5: J1.213(A5) ; also on sheet 13
DDR4_DDIMM2_A6: J1.69(A6) ; also on sheet 13
DDR4_DDIMM2_A7: J1.211(A7) ; also on sheet 13
DDR4_DDIMM2_A8: J1.68(A8) ; also on sheet 13
DDR4_DDIMM2_A9: J1.66(A9) ; also on sheet 13
DDR4_DDIMM2_A10: J1.225(A10/AP) ; also on sheet 13
DDR4_DDIMM2_A11: J1.210(A11) ; also on sheet 13
DDR4_DDIMM2_A12: J1.65(A12) ; also on sheet 13
DDR4_DDIMM2_A13: J1.232(A13) ; also on sheet 13
DDR4_DDIMM2_A14: J1.228(WE_n/A14) ; also on sheet 13
DDR4_DDIMM2_A15: J1.86(CAS_n/A15) ; also on sheet 13
DDR4_DDIMM2_A16: J1.82(RAS_n/A16) ; also on sheet 13
DDR4_DDIMM2_A17: J1.234(A17/NC) ; also on sheet 13
DDR4_DDIMM2_ACT_N: J1.62(ACT_n) ; also on sheet 13
DDR4_DDIMM2_ALERT_N: J1.208(ALERT_n) R91.1 ; also on sheet 13
DDR4_DDIMM2_BA0: J1.81(BA0) ; also on sheet 13
DDR4_DDIMM2_BA1: J1.224(BA1) ; also on sheet 13
DDR4_DDIMM2_BG0: J1.63(BG0) ; also on sheet 13
DDR4_DDIMM2_BG1: J1.207(BG1) ; also on sheet 13
DDR4_DDIMM2_C0_CS_N2: J1.93(S2_n/C0) ; also on sheet 13
DDR4_DDIMM2_C1_CS_N3: J1.237(S3_n/C1) ; also on sheet 13
DDR4_DDIMM2_DBI_N0: J1.7(DQS9_t/DM0_n/DBI0_n) ; also on sheet 12
DDR4_DDIMM2_DBI_N1: J1.18(DQS10_t/DM1_n/DBI1_n) ; also on sheet 13
DDR4_DDIMM2_DBI_N2: J1.29(DQS11_t/DM2_n/DBI2_n) ; also on sheet 12
DDR4_DDIMM2_DBI_N3: J1.40(DQS12_t/DM3_n/DBI3_n) ; also on sheet 13
DDR4_DDIMM2_DBI_N4: J1.99(DQS13_t/DM4_n/DBI4_n) ; also on sheet 13
DDR4_DDIMM2_DBI_N5: J1.110(DQS14_t/DM5_n/DBI5_n) ; also on sheet 12
DDR4_DDIMM2_DBI_N6: J1.121(DQS15_t/DM6_n/DBI6_n) ; also on sheet 12
DDR4_DDIMM2_DBI_N7: J1.132(DQS16_t/DM7_n/DBI7_n) ; also on sheet 12
DDR4_DDIMM2_DBI_N8: J1.51(DQS17_t/DM8_n/DBI8_n) ; also on sheet 13
DDR4_DDIMM2_DQ0: J1.5(DQ0) ; also on sheet 12
DDR4_DDIMM2_DQ1: J1.150(DQ1) ; also on sheet 12
DDR4_DDIMM2_DQ2: J1.12(DQ2) ; also on sheet 12
DDR4_DDIMM2_DQ3: J1.157(DQ3) ; also on sheet 12
DDR4_DDIMM2_DQ4: J1.3(DQ4) ; also on sheet 12
DDR4_DDIMM2_DQ5: J1.148(DQ5) ; also on sheet 12
DDR4_DDIMM2_DQ6: J1.10(DQ6) ; also on sheet 12
DDR4_DDIMM2_DQ7: J1.155(DQ7) ; also on sheet 12
DDR4_DDIMM2_DQ8: J1.16(DQ8) ; also on sheet 13
DDR4_DDIMM2_DQ9: J1.161(DQ9) ; also on sheet 13
DDR4_DDIMM2_DQ10: J1.23(DQ10) ; also on sheet 13
DDR4_DDIMM2_DQ11: J1.168(DQ11) ; also on sheet 13
DDR4_DDIMM2_DQ12: J1.14(DQ12) ; also on sheet 13
DDR4_DDIMM2_DQ13: J1.159(DQ13) ; also on sheet 13
DDR4_DDIMM2_DQ14: J1.21(DQ14) ; also on sheet 13
DDR4_DDIMM2_DQ15: J1.166(DQ15) ; also on sheet 13
DDR4_DDIMM2_DQ16: J1.27(DQ16) ; also on sheet 12
DDR4_DDIMM2_DQ17: J1.172(DQ17) ; also on sheet 12
DDR4_DDIMM2_DQ18: J1.34(DQ18) ; also on sheet 12
DDR4_DDIMM2_DQ19: J1.179(DQ19) ; also on sheet 12
DDR4_DDIMM2_DQ20: J1.25(DQ20) ; also on sheet 12
DDR4_DDIMM2_DQ21: J1.170(DQ21) ; also on sheet 12
DDR4_DDIMM2_DQ22: J1.32(DQ22) ; also on sheet 12
DDR4_DDIMM2_DQ23: J1.177(DQ23) ; also on sheet 12
DDR4_DDIMM2_DQ24: J1.38(DQ24) ; also on sheet 13
DDR4_DDIMM2_DQ25: J1.183(DQ25) ; also on sheet 13
DDR4_DDIMM2_DQ26: J1.45(DQ26) ; also on sheet 13
DDR4_DDIMM2_DQ27: J1.190(DQ27) ; also on sheet 13
DDR4_DDIMM2_DQ28: J1.36(DQ28) ; also on sheet 13
DDR4_DDIMM2_DQ29: J1.181(DQ29) ; also on sheet 13
DDR4_DDIMM2_DQ30: J1.43(DQ30) ; also on sheet 13
DDR4_DDIMM2_DQ31: J1.188(DQ31) ; also on sheet 13
DDR4_DDIMM2_DQ32: J1.97(DQ32) ; also on sheet 13
DDR4_DDIMM2_DQ33: J1.242(DQ33) ; also on sheet 13
DDR4_DDIMM2_DQ34: J1.104(DQ34) ; also on sheet 13
DDR4_DDIMM2_DQ35: J1.249(DQ35) ; also on sheet 13
DDR4_DDIMM2_DQ36: J1.95(DQ36) ; also on sheet 13
DDR4_DDIMM2_DQ37: J1.240(DQ37) ; also on sheet 13
DDR4_DDIMM2_DQ38: J1.102(DQ38) ; also on sheet 13
DDR4_DDIMM2_DQ39: J1.247(DQ39) ; also on sheet 13
DDR4_DDIMM2_DQ40: J1.108(DQ40) ; also on sheet 12
DDR4_DDIMM2_DQ41: J1.253(DQ41) ; also on sheet 12
DDR4_DDIMM2_DQ42: J1.115(DQ42) ; also on sheet 12
DDR4_DDIMM2_DQ43: J1.260(DQ43) ; also on sheet 12
DDR4_DDIMM2_DQ44: J1.106(DQ44) ; also on sheet 12
DDR4_DDIMM2_DQ45: J1.251(DQ45) ; also on sheet 12
DDR4_DDIMM2_DQ46: J1.113(DQ46) ; also on sheet 12
DDR4_DDIMM2_DQ47: J1.258(DQ47) ; also on sheet 12
DDR4_DDIMM2_DQ48: J1.119(DQ48) ; also on sheet 12
DDR4_DDIMM2_DQ49: J1.264(DQ49) ; also on sheet 12
DDR4_DDIMM2_DQ50: J1.126(DQ50) ; also on sheet 12
DDR4_DDIMM2_DQ51: J1.271(DQ51) ; also on sheet 12
DDR4_DDIMM2_DQ52: J1.117(DQ52) ; also on sheet 12
DDR4_DDIMM2_DQ53: J1.262(DQ53) ; also on sheet 12
DDR4_DDIMM2_DQ54: J1.124(DQ54) ; also on sheet 12
DDR4_DDIMM2_DQ55: J1.269(DQ55) ; also on sheet 12
DDR4_DDIMM2_DQ56: J1.130(DQ56) ; also on sheet 12
DDR4_DDIMM2_DQ57: J1.275(DQ57) ; also on sheet 12
DDR4_DDIMM2_DQ58: J1.137(DQ58) ; also on sheet 12
DDR4_DDIMM2_DQ59: J1.282(DQ59) ; also on sheet 12
DDR4_DDIMM2_DQ60: J1.128(DQ60) ; also on sheet 12
DDR4_DDIMM2_DQ61: J1.273(DQ61) ; also on sheet 12
DDR4_DDIMM2_DQ62: J1.135(DQ62) ; also on sheet 12
DDR4_DDIMM2_DQ63: J1.280(DQ63) ; also on sheet 12
DDR4_DDIMM2_DQ64: J1.49(CB0/NC) ; also on sheet 13
DDR4_DDIMM2_DQ65: J1.194(CB1/NC) ; also on sheet 13
DDR4_DDIMM2_DQ66: J1.56(CB2/NC) ; also on sheet 13
DDR4_DDIMM2_DQ67: J1.201(CB3/NC) ; also on sheet 13
DDR4_DDIMM2_DQ68: J1.47(CB4/NC) ; also on sheet 13
DDR4_DDIMM2_DQ69: J1.192(CB5/NC) ; also on sheet 13
DDR4_DDIMM2_DQ70: J1.54(CB6/NC) ; also on sheet 13
DDR4_DDIMM2_DQ71: J1.199(CB7/NC) ; also on sheet 13
DDR4_DDIMM2_DQS_N0: J1.152(DQS0_c) ; also on sheet 12
DDR4_DDIMM2_DQS_N1: J1.163(DQS1_c) ; also on sheet 13
DDR4_DDIMM2_DQS_N2: J1.174(DQS2_c) ; also on sheet 12
DDR4_DDIMM2_DQS_N3: J1.185(DQS3_c) ; also on sheet 13
DDR4_DDIMM2_DQS_N4: J1.244(DQS4_c) ; also on sheet 13
DDR4_DDIMM2_DQS_N5: J1.255(DQS5_c) ; also on sheet 12
DDR4_DDIMM2_DQS_N6: J1.266(DQS6_c) ; also on sheet 12
DDR4_DDIMM2_DQS_N7: J1.277(DQS7_c) ; also on sheet 12
DDR4_DDIMM2_DQS_N8: J1.196(DQS8_c) ; also on sheet 13
DDR4_DDIMM2_DQS_P0: J1.153(DQS0_t) ; also on sheet 12
DDR4_DDIMM2_DQS_P1: J1.164(DQS1_t) ; also on sheet 13
DDR4_DDIMM2_DQS_P2: J1.175(DQS2_t) ; also on sheet 12
DDR4_DDIMM2_DQS_P3: J1.186(DQS3_t) ; also on sheet 13
DDR4_DDIMM2_DQS_P4: J1.245(DQS4_t) ; also on sheet 13
DDR4_DDIMM2_DQS_P5: J1.256(DQS5_t) ; also on sheet 12
DDR4_DDIMM2_DQS_P6: J1.267(DQS6_t) ; also on sheet 12
DDR4_DDIMM2_DQS_P7: J1.278(DQS7_t) ; also on sheet 12
DDR4_DDIMM2_DQS_P8: J1.197(DQS8_t) ; also on sheet 13
DDR4_DDIMM2_PAR: J1.222(PARITY) ; also on sheet 13
DDR4_DDIMM2_RESET_N: J1.58(RESET_n) R87.1 R88.2 ; also on sheet 13
DDR4_DDIMM2_TDQS_N9: J1.8(DQS9_c) ; also on sheet 12
DDR4_DDIMM2_TDQS_N10: J1.19(DQS10_c) ; also on sheet 13
DDR4_DDIMM2_TDQS_N11: J1.30(DQS11_c) ; also on sheet 12
DDR4_DDIMM2_TDQS_N12: J1.41(DQS12_c) ; also on sheet 13
DDR4_DDIMM2_TDQS_N13: J1.100(DQS13_c) ; also on sheet 13
DDR4_DDIMM2_TDQS_N14: J1.111(DQS14_c) ; also on sheet 12
DDR4_DDIMM2_TDQS_N15: J1.122(DQS15_c) ; also on sheet 12
DDR4_DDIMM2_TDQS_N16: J1.133(DQS16_c) ; also on sheet 12
DDR4_DDIMM2_TDQS_N17: J1.52(DQS17_c) ; also on sheet 13
DDR4_DDIMM_A0: J2.79(A0) U6.LH42(IO,_DIFF_TX_2F21P,_DQ22)
DDR4_DDIMM_A1: J2.72(A1) U6.LL43(IO,_DIFF_TX_2F21N,_DQ22)
DDR4_DDIMM_A2: J2.216(A2) U6.KW43(IO,_CDR,_DIFF_RX_2F21P,_DQ22)
DDR4_DDIMM_A3: J2.71(A3) U6.LB42(IO,_CDR,_DIFF_RX_2F21N,_DQ22)
DDR4_DDIMM_A4: J2.214(A4) U6.LH40(IO,_DIFF_TX_2F20P,_DQS22)
DDR4_DDIMM_A5: J2.213(A5) U6.LL41(IO,_DIFF_TX_2F20N,_DQSN22)
DDR4_DDIMM_A6: J2.69(A6) U6.LB40(IO,_PLL_2F_B_CLKOUT0P,_PLL_2F_B_CLKOUT0,_PLL_2F_B_FB0,_DIFF_RX_2F20P,_DQ22)
DDR4_DDIMM_A7: J2.211(A7) U6.KW41(IO,_PLL_2F_B_CLKOUT0N,_DIFF_RX_2F20N,_DQ22)
DDR4_DDIMM_A8: J2.68(A8) U6.LH38(IO,_DIFF_TX_2F19P,_DQ22)
DDR4_DDIMM_A9: J2.66(A9) U6.LL39(IO,_DIFF_TX_2F19N,_DQ22)
DDR4_DDIMM_A10: J2.225(A10/AP) U6.KW39(IO,_CLK_B_2F_0P,_CDR,_DIFF_RX_2F19P,_DQ22)
DDR4_DDIMM_A11: J2.210(A11) U6.LB38(IO,_CLK_B_2F_0N,_CDR,_DIFF_RX_2F19N,_DQ22)
DDR4_DDIMM_A12: J2.65(A12) U6.KF36(IO,_CDR,_DIFF_RX_2F18N,_DQ21)
DDR4_DDIMM_A13: J2.232(A13) U6.KU34(IO,_PLL_2F_B_CLKOUT1P,_PLL_2F_B_CLKOUT1,_PLL_2F_B_FB1,_DIFF_TX_2F17P,_DQS21)
DDR4_DDIMM_A14: J2.228(WE_n/A14) U6.KR35(IO,_PLL_2F_B_CLKOUT1N,_DIFF_TX_2F17N,_DQSN21)
DDR4_DDIMM_A15: J2.86(CAS_n/A15) U6.KF34(IO,_DIFF_RX_2F17P,_DQ21)
DDR4_DDIMM_A16: J2.82(RAS_n/A16) U6.KJ35(IO,_DIFF_RX_2F17N,_DQ21)
DDR4_DDIMM_A17: J2.234(A17/NC) U6.KU32(IO,_DIFF_TX_2F16P,_DQ21)
DDR4_DDIMM_ACT_N: J2.62(ACT_n) U6.KJ43(IO,_CDR,_DIFF_RX_2F24N,_DQ23)
DDR4_DDIMM_ALERT_N: J2.208(ALERT_n) R1049.1 U6.KC33(IO,_DIFF_TX_2F13P,_DQ20)
DDR4_DDIMM_BA0: J2.81(BA0) U6.KR33(IO,_DIFF_TX_2F16N,_DQ21)
DDR4_DDIMM_BA1: J2.224(BA1) U6.KJ33(IO,_CDR,_DIFF_RX_2F16P,_DQ21)
DDR4_DDIMM_BG0: J2.63(BG0) U6.KF32(IO,_CDR,_DIFF_RX_2F16N,_DQ21)
DDR4_DDIMM_BG1: J2.207(BG1) U6.KR43(IO,_DIFF_TX_2F24P,_DQ23)
DDR4_DDIMM_C0: R1070.1 U6.KC37(IO,_DIFF_TX_2F15P,_DQ20)
DDR4_DDIMM_C0_CS_N2: J2.93(S2_n/C0) R1070.2 R1072.2
DDR4_DDIMM_C1: R1071.1 U6.JY36(IO,_DIFF_TX_2F15N,_DQ20)
DDR4_DDIMM_C1_CS_N3: J2.237(S3_n/C1) R1071.2 R1073.2
DDR4_DDIMM_CK_N0: J2.75(CK0_c) U6.KU38(IO,_DIFF_TX_2F22N,_DQ23)
DDR4_DDIMM_CK_N1: J2.219(CK1_c) U6.JL33(IO,_CDR,_DIFF_RX_2F13N,_DQ20)
DDR4_DDIMM_CK_P0: J2.74(CK0_t) U6.KR39(IO,_DIFF_TX_2F22P,_DQ23)
DDR4_DDIMM_CK_P1: J2.218(CK1_t) U6.JP32(IO,_CDR,_DIFF_RX_2F13P,_DQ20)
DDR4_DDIMM_CKE0: J2.60(CKE0) R103.2 U6.KF40(IO,_DIFF_RX_2F23P,_DQ23)
DDR4_DDIMM_CKE1: J2.203(CKE1) R104.2 U6.KJ41(IO,_DIFF_RX_2F23N,_DQ23)
DDR4_DDIMM_CS_N0: J2.84(S0_n) U6.KF42(IO,_CDR,_DIFF_RX_2F24P,_DQ23)
DDR4_DDIMM_CS_N1: J2.89(S1_n) U6.KF38(IO,_CDR,_DIFF_RX_2F22P,_DQ23)
DDR4_DDIMM_CS_N2: R1072.1 U6.JP34(IO,_DIFF_RX_2F14P,_DQ20)
DDR4_DDIMM_CS_N3: R1073.1 U6.JL35(IO,_DIFF_RX_2F14N,_DQ20)
DDR4_DDIMM_DBI_N0: J2.7(DQS9_t/DM0_n/DBI0_n) U6.LR17(IO,_PLL_2C_T_CLKOUT0P,_PLL_2C_T_CLKOUT0,_PLL_2C_T_FB0,_DIFF_RX_2C8P,_DQ10)
DDR4_DDIMM_DBI_N1: J2.18(DQS10_t/DM1_n/DBI1_n) U6.MD23(IO,_DIFF_RX_2C11P,_DQ11)
DDR4_DDIMM_DBI_N2: J2.29(DQS11_t/DM2_n/DBI2_n) U6.LR5(IO,_DIFF_RX_2C2P,_DQ8)
DDR4_DDIMM_DBI_N3: J2.40(DQS12_t/DM3_n/DBI3_n) U6.MD11(IO,_DIFF_RX_2C5P,_DQ9)
DDR4_DDIMM_DBI_N4: J2.99(DQS13_t/DM4_n/DBI4_n) U6.LR27(IO,_DIFF_RX_2F2P,_DQ16)
DDR4_DDIMM_DBI_N5: J2.110(DQS14_t/DM5_n/DBI5_n) U6.LR33(IO,_DIFF_RX_2F11P,_DQ19)
DDR4_DDIMM_DBI_N6: J2.121(DQS15_t/DM6_n/DBI6_n) U6.LB28(IO,_DIFF_RX_2C23P,_DQ15)
DDR4_DDIMM_DBI_N7: J2.132(DQS16_t/DM7_n/DBI7_n) U6.LB34(IO,_PLL_2F_T_CLKOUT0P,_PLL_2F_T_CLKOUT0,_PLL_2F_T_FB0,_DIFF_RX_2F8P,_DQ18)
DDR4_DDIMM_DBI_N8: J2.51(DQS17_t/DM8_n/DBI8_n) U6.MD30(IO,_DIFF_RX_2F5P,_DQ17)
DDR4_DDIMM_DQ0: J2.5(DQ0) U6.LR21(IO,_CDR,_DIFF_RX_2C9P,_DQ10)
DDR4_DDIMM_DQ1: J2.150(DQ1) U6.LN23(IO,_CDR,_DIFF_RX_2C9N,_DQ10)
DDR4_DDIMM_DQ2: J2.12(DQ2) U6.LW21(IO,_DIFF_TX_2C9N,_DQ10)
DDR4_DDIMM_DQ3: J2.157(DQ3) U6.MA23(IO,_DIFF_TX_2C9P,_DQ10)
DDR4_DDIMM_DQ4: J2.3(DQ4) U6.LW13(IO,_DIFF_TX_2C7N,_DQ10)
DDR4_DDIMM_DQ5: J2.148(DQ5) U6.MA15(IO,_DIFF_TX_2C7P,_DQ10)
DDR4_DDIMM_DQ6: J2.10(DQ6) U6.LR13(IO,_CLK_T_2C_0P,_DIFF_RX_2C7P,_DQ10)
DDR4_DDIMM_DQ7: J2.155(DQ7) U6.LN15(IO,_CLK_T_2C_0N,_DIFF_RX_2C7N,_DQ10)
DDR4_DDIMM_DQ8: J2.16(DQ8) U6.MH26(IO,_DIFF_TX_2C12N,_DQ11)
DDR4_DDIMM_DQ9: J2.161(DQ9) U6.MK27(IO,_DIFF_TX_2C12P,_DQ11)
DDR4_DDIMM_DQ10: J2.23(DQ10) U6.MD26(IO,_CDR,_DIFF_RX_2C12N,_DQ11)
DDR4_DDIMM_DQ11: J2.168(DQ11) U6.MC27(IO,_CDR,_DIFF_RX_2C12P,_DQ11)
DDR4_DDIMM_DQ12: J2.14(DQ12) U6.MH19(IO,_DIFF_TX_2C10N,_DQ11)
DDR4_DDIMM_DQ13: J2.159(DQ13) U6.MD19(IO,_DIFF_RX_2C10P,_DQ11)
DDR4_DDIMM_DQ14: J2.21(DQ14) U6.MK21(IO,_DIFF_TX_2C10P,_DQ11)
DDR4_DDIMM_DQ15: J2.166(DQ15) U6.MC21(IO,_DIFF_RX_2C10N,_DQ11)
DDR4_DDIMM_DQ16: J2.27(DQ16) U6.LR9(IO,_CDR,_DIFF_RX_2C3P,_DQ8)
DDR4_DDIMM_DQ17: J2.172(DQ17) U6.LW9(IO,_DIFF_TX_2C3N,_DQ8)
DDR4_DDIMM_DQ18: J2.34(DQ18) U6.LN11(IO,_CDR,_DIFF_RX_2C3N,_DQ8)
DDR4_DDIMM_DQ19: J2.179(DQ19) U6.MA11(IO,_DIFF_TX_2C3P,_DQ8)
DDR4_DDIMM_DQ20: J2.25(DQ20) U6.LU4(IO,_DIFF_RX_2C1N,_DQ8)
DDR4_DDIMM_DQ21: J2.170(DQ21) U6.LW2(IO,_DIFF_RX_2C1P,_DQ8)
DDR4_DDIMM_DQ22: J2.32(DQ22) U6.MA4(IO,_DIFF_TX_2C1N,_DQ8)
DDR4_DDIMM_DQ23: J2.177(DQ23) U6.MC5(IO,_DIFF_TX_2C1P,_DQ8)
DDR4_DDIMM_DQ24: J2.38(DQ24) U6.MH15(IO,_CLK_T_2C_1N,_DIFF_TX_2C6N,_DQ9)
DDR4_DDIMM_DQ25: J2.183(DQ25) U6.MD15(IO,_CDR,_DIFF_RX_2C6N,_DQ9)
DDR4_DDIMM_DQ26: J2.45(DQ26) U6.MC17(IO,_RZQ_T_2C,_CDR,_DIFF_RX_2C6P,_DQ9)
DDR4_DDIMM_DQ27: J2.190(DQ27) U6.MK17(IO,_CLK_T_2C_1P,_DIFF_TX_2C6P,_DQ9)
DDR4_DDIMM_DQ28: J2.36(DQ28) U6.MF5(IO,_DIFF_TX_2C4N,_DQ9)
DDR4_DDIMM_DQ29: J2.181(DQ29) U6.MD7(IO,_DIFF_RX_2C4P,_DQ9)
DDR4_DDIMM_DQ30: J2.43(DQ30) U6.MC9(IO,_DIFF_RX_2C4N,_DQ9)
DDR4_DDIMM_DQ31: J2.188(DQ31) U6.MH7(IO,_DIFF_TX_2C4P,_DQ9)
DDR4_DDIMM_DQ32: J2.97(DQ32) U6.LW29(IO,_DIFF_TX_2F3N,_DQ16)
DDR4_DDIMM_DQ33: J2.242(DQ33) U6.LR29(IO,_CDR,_DIFF_RX_2F3N,_DQ16)
DDR4_DDIMM_DQ34: J2.104(DQ34) U6.LN30(IO,_CDR,_DIFF_RX_2F3P,_DQ16)
DDR4_DDIMM_DQ35: J2.249(DQ35) U6.MA30(IO,_DIFF_TX_2F3P,_DQ16)
DDR4_DDIMM_DQ36: J2.95(DQ36) U6.LN26(IO,_DIFF_RX_2F1N,_DQ16)
DDR4_DDIMM_DQ37: J2.240(DQ37) U6.MA26(IO,_DIFF_TX_2F1P,_DQ16)
DDR4_DDIMM_DQ38: J2.102(DQ38) U6.LW25(IO,_DIFF_TX_2F1N,_DQ16)
DDR4_DDIMM_DQ39: J2.247(DQ39) U6.LR25(IO,_DIFF_RX_2F1P,_DQ16)
DDR4_DDIMM_DQ40: J2.108(DQ40) U6.LW35(IO,_DIFF_TX_2F12N,_DQ19)
DDR4_DDIMM_DQ41: J2.253(DQ41) U6.LR35(IO,_CDR,_DIFF_RX_2F12P,_DQ19)
DDR4_DDIMM_DQ42: J2.115(DQ42) U6.MA36(IO,_DIFF_TX_2F12P,_DQ19)
DDR4_DDIMM_DQ43: J2.260(DQ43) U6.LN36(IO,_CDR,_DIFF_RX_2F12N,_DQ19)
DDR4_DDIMM_DQ44: J2.106(DQ44) U6.LR31(IO,_DIFF_RX_2F10P,_DQ19)
DDR4_DDIMM_DQ45: J2.251(DQ45) U6.LW31(IO,_DIFF_TX_2F10N,_DQ19)
DDR4_DDIMM_DQ46: J2.113(DQ46) U6.LN32(IO,_DIFF_RX_2F10N,_DQ19)
DDR4_DDIMM_DQ47: J2.258(DQ47) U6.MA32(IO,_DIFF_TX_2F10P,_DQ19)
DDR4_DDIMM_DQ48: J2.119(DQ48) U6.LH30(IO,_DIFF_TX_2C24N,_DQ15)
DDR4_DDIMM_DQ49: J2.264(DQ49) U6.KW31(IO,_CDR,_DIFF_RX_2C24N,_DQ15)
DDR4_DDIMM_DQ50: J2.126(DQ50) U6.LB30(IO,_CDR,_DIFF_RX_2C24P,_DQ15)
DDR4_DDIMM_DQ51: J2.271(DQ51) U6.LL31(IO,_DIFF_TX_2C24P,_DQ15)
DDR4_DDIMM_DQ52: J2.117(DQ52) U6.KW27(IO,_CDR,_DIFF_RX_2C22N,_DQ15)
DDR4_DDIMM_DQ53: J2.262(DQ53) U6.LH26(IO,_DIFF_TX_2C22N,_DQ15)
DDR4_DDIMM_DQ54: J2.124(DQ54) U6.LB26(IO,_CDR,_DIFF_RX_2C22P,_DQ15)
DDR4_DDIMM_DQ55: J2.269(DQ55) U6.LL27(IO,_DIFF_TX_2C22P,_DQ15)
DDR4_DDIMM_DQ56: J2.130(DQ56) U6.LH36(IO,_DIFF_TX_2F9N,_DQ18)
DDR4_DDIMM_DQ57: J2.275(DQ57) U6.LB36(IO,_CDR,_DIFF_RX_2F9P,_DQ18)
DDR4_DDIMM_DQ58: J2.137(DQ58) U6.LL37(IO,_DIFF_TX_2F9P,_DQ18)
DDR4_DDIMM_DQ59: J2.282(DQ59) U6.KW37(IO,_CDR,_DIFF_RX_2F9N,_DQ18)
DDR4_DDIMM_DQ60: J2.128(DQ60) U6.LB32(IO,_CLK_T_2F_0P,_DIFF_RX_2F7P,_DQ18)
DDR4_DDIMM_DQ61: J2.273(DQ61) U6.LL33(IO,_DIFF_TX_2F7P,_DQ18)
DDR4_DDIMM_DQ62: J2.135(DQ62) U6.LH32(IO,_DIFF_TX_2F7N,_DQ18)
DDR4_DDIMM_DQ63: J2.280(DQ63) U6.KW33(IO,_CLK_T_2F_0N,_DIFF_RX_2F7N,_DQ18)
DDR4_DDIMM_DQ64: J2.49(CB0/NC) U6.MD32(IO,_CDR,_DIFF_RX_2F6N,_DQ17)
DDR4_DDIMM_DQ65: J2.194(CB1/NC) U6.MH32(IO,_CLK_T_2F_1N,_DIFF_TX_2F6N,_DQ17)
DDR4_DDIMM_DQ66: J2.56(CB2/NC) U6.MK33(IO,_CLK_T_2F_1P,_DIFF_TX_2F6P,_DQ17)
DDR4_DDIMM_DQ67: J2.201(CB3/NC) U6.MC33(IO,_RZQ_T_2F,_CDR,_DIFF_RX_2F6P,_DQ17)
DDR4_DDIMM_DQ68: J2.47(CB4/NC) U6.MD28(IO,_DIFF_RX_2F4P,_DQ17)
DDR4_DDIMM_DQ69: J2.192(CB5/NC) U6.MH28(IO,_DIFF_TX_2F4N,_DQ17)
DDR4_DDIMM_DQ70: J2.54(CB6/NC) U6.MK29(IO,_DIFF_TX_2F4P,_DQ17)
DDR4_DDIMM_DQ71: J2.199(CB7/NC) U6.MC29(IO,_DIFF_RX_2F4N,_DQ17)
DDR4_DDIMM_DQS_N0: J2.152(DQS0_c) U6.MA19(IO,_DIFF_TX_2C8N,_DQSN10)
DDR4_DDIMM_DQS_N1: J2.163(DQS1_c) U6.MK25(IO,_DIFF_TX_2C11N,_DQSN11)
DDR4_DDIMM_DQS_N2: J2.174(DQS2_c) U6.MA7(IO,_DIFF_TX_2C2N,_DQSN8)
DDR4_DDIMM_DQS_N3: J2.185(DQS3_c) U6.MK13(IO,_PLL_2C_T_CLKOUT1N,_DIFF_TX_2C5N,_DQSN9)
DDR4_DDIMM_DQS_N4: J2.244(DQS4_c) U6.MA28(IO,_DIFF_TX_2F2N,_DQSN16)
DDR4_DDIMM_DQS_N5: J2.255(DQS5_c) U6.MA34(IO,_DIFF_TX_2F11N,_DQSN19)
DDR4_DDIMM_DQS_N6: J2.266(DQS6_c) U6.LL29(IO,_DIFF_TX_2C23N,_DQSN15)
DDR4_DDIMM_DQS_N7: J2.277(DQS7_c) U6.LL35(IO,_DIFF_TX_2F8N,_DQSN18)
DDR4_DDIMM_DQS_N8: J2.196(DQS8_c) U6.MK31(IO,_PLL_2F_T_CLKOUT1N,_DIFF_TX_2F5N,_DQSN17)
DDR4_DDIMM_DQS_P0: J2.153(DQS0_t) U6.LW17(IO,_DIFF_TX_2C8P,_DQS10)
DDR4_DDIMM_DQS_P1: J2.164(DQS1_t) U6.MH23(IO,_DIFF_TX_2C11P,_DQS11)
DDR4_DDIMM_DQS_P2: J2.175(DQS2_t) U6.LW5(IO,_DIFF_TX_2C2P,_DQS8)
DDR4_DDIMM_DQS_P3: J2.186(DQS3_t) U6.MH11(IO,_PLL_2C_T_CLKOUT1P,_PLL_2C_T_CLKOUT1,_PLL_2C_T_FB1,_DIFF_TX_2C5P,_DQS9)
DDR4_DDIMM_DQS_P4: J2.245(DQS4_t) U6.LW27(IO,_DIFF_TX_2F2P,_DQS16)
DDR4_DDIMM_DQS_P5: J2.256(DQS5_t) U6.LW33(IO,_DIFF_TX_2F11P,_DQS19)
DDR4_DDIMM_DQS_P6: J2.267(DQS6_t) U6.LH28(IO,_DIFF_TX_2C23P,_DQS15)
DDR4_DDIMM_DQS_P7: J2.278(DQS7_t) U6.LH34(IO,_DIFF_TX_2F8P,_DQS18)
DDR4_DDIMM_DQS_P8: J2.197(DQS8_t) U6.MH30(IO,_PLL_2F_T_CLKOUT1P,_PLL_2F_T_CLKOUT1,_PLL_2F_T_FB1,_DIFF_TX_2F5P,_DQS17)
DDR4_DDIMM_EVENT_N: J2.78(EVENT_n) R99.1 U13.13(IOVCC1)
DDR4_DDIMM_ODT0: J2.87(ODT0) U6.KU40(IO,_DIFF_TX_2F23P,_DQS23)
DDR4_DDIMM_ODT1: J2.91(ODT1) U6.KR41(IO,_DIFF_TX_2F23N,_DQSN23)
DDR4_DDIMM_PAR: J2.222(PARITY) U6.KJ39(IO,_CDR,_DIFF_RX_2F22N,_DQ23)
DDR4_DDIMM_RESET_N: J2.58(RESET_n) R1047.1 R1048.2 U6.KU42(IO,_DIFF_TX_2F24N,_DQ23)
DDR4_DDIMM_RZQ: R75.1 U6.KJ37(IO,_RZQ_B_2F,_CDR,_DIFF_RX_2F18P,_DQ21)
DDR4_DDIMM_SA0: J2.139(SA0) R100.1
DDR4_DDIMM_SA1: J2.140(SA1) R101.2
DDR4_DDIMM_SA2: J2.238(SA2/RFU) R102.2
DDR4_DDIMM_SAVE_N: J2.230(SAVE_n/NC) R98.1 U13.12(IOVCC2)
DDR4_DDIMM_TDQS_N9: J2.8(DQS9_c) U6.LN19(IO,_PLL_2C_T_CLKOUT0N,_DIFF_RX_2C8N,_DQ10)
DDR4_DDIMM_TDQS_N10: J2.19(DQS10_c) U6.MC25(IO,_DIFF_RX_2C11N,_DQ11)
DDR4_DDIMM_TDQS_N11: J2.30(DQS11_c) U6.LN7(IO,_DIFF_RX_2C2N,_DQ8)
DDR4_DDIMM_TDQS_N12: J2.41(DQS12_c) U6.MC13(IO,_DIFF_RX_2C5N,_DQ9)
DDR4_DDIMM_TDQS_N13: J2.100(DQS13_c) U6.LN28(IO,_DIFF_RX_2F2N,_DQ16)
DDR4_DDIMM_TDQS_N14: J2.111(DQS14_c) U6.LN34(IO,_DIFF_RX_2F11N,_DQ19)
DDR4_DDIMM_TDQS_N15: J2.122(DQS15_c) U6.KW29(IO,_DIFF_RX_2C23N,_DQ15)
DDR4_DDIMM_TDQS_N16: J2.133(DQS16_c) U6.KW35(IO,_PLL_2F_T_CLKOUT0N,_DIFF_RX_2F8N,_DQ18)
DDR4_DDIMM_TDQS_N17: J2.52(DQS17_c) U6.MC31(IO,_DIFF_RX_2F5N,_DQ17)
DDR4_DIMM2_CK_N0: J1.75(CK0_c) ; also on sheet 13
DDR4_DIMM2_CK_N1: J1.219(CK1_c) ; also on sheet 13
DDR4_DIMM2_CK_P0: J1.74(CK0_t) ; also on sheet 13
DDR4_DIMM2_CK_P1: J1.218(CK1_t) ; also on sheet 13
DDR4_DIMM2_CKE0: J1.60(CKE0) R89.2 ; also on sheet 13
DDR4_DIMM2_CKE1: J1.203(CKE1) R90.2 ; also on sheet 13
DDR4_DIMM2_CS_N0: J1.84(S0_n) ; also on sheet 13
DDR4_DIMM2_CS_N1: J1.89(S1_n) ; also on sheet 13
DDR4_DIMM2_EVENT_N: J1.78(EVENT_n) R83.1 U12.13(IOVCC1)
DDR4_DIMM2_ODT0: J1.87(ODT0) ; also on sheet 13
DDR4_DIMM2_ODT1: J1.91(ODT1) ; also on sheet 13
DDR4_DIMM2_SA0: J1.139(SA0) R84.2 R1068.1
DDR4_DIMM2_SA1: J1.140(SA1) R85.2 R1069.1
DDR4_DIMM2_SA2: J1.238(SA2/RFU) R86.2
DDR4_DIMM2_SAVE_N: J1.230(SAVE_n/NC) R82.1 U12.12(IOVCC2)
DDR4_DIMM_SCL: J1.141(SCL) J2.141(SCL) U12.11(IOVCC3) ; also on sheet 46
DDR4_DIMM_SDA: J1.285(SDA) J2.285(SDA) U12.10(IOVCC4) ; also on sheet 46
FPGA_CXL_PRSNTx1_N: R6302.2 ; also on sheet 32
FPGA_CXL_PRSNTx4_N: R6305.2 ; also on sheet 32
FPGA_CXL_PRSNTx8_N: U6.JY26(IO,_DIFF_TX_2C16N,_DQ13) ; also on sheet 32
FPGA_CXL_PRSNTx16_N: U6.KC27(IO,_DIFF_TX_2C16P,_DQ13) ; also on sheet 32
FPGA_DDIMM_EVENT_N: U6.KR29(IO,_DIFF_TX_2C20N,_DQSN14) U13.2(IOVL1)
FPGA_DDIMM_SAVE_N: U6.KF30(IO,_CDR,_DIFF_RX_2C21N,_DQ14) U13.3(IOVL2)
FPGA_DIMM2_EVENT_N: U12.2(IOVL1) ; also on sheet 12
FPGA_DIMM2_SAVE_N: U12.3(IOVL2) ; also on sheet 12
FPGA_DIMM_SCL: R80.1 U6.KC29(IO,_PLL_2C_B_CLKOUT1N,_DIFF_TX_2C17N,_DQSN13) U12.4(IOVL3)
FPGA_DIMM_SDA: R81.1 U6.KJ27(IO,_CLK_B_2C_0P,_CDR,_DIFF_RX_2C19P,_DQ14) U12.5(IOVL4)
N17328275: J1.1(12V/NC) J1.145(12V/NC) R77.2 R78.2
N17329090: J1.288(Vpp) R94.2
N40803427: J1.235(C2/NC) R79.2
N40814737: J2.1(12V/NC) J2.145(12V/NC) R95.2 R96.2
N40815384: J2.235(C2/NC) R97.2
N40816526: J2.288(Vpp) R107.2
N51915113: R6304.1 R6305.1 U6.JP26(IO,_CDR,_DIFF_RX_2C16P,_DQ13)
N51915123: R6302.1 R6303.1 U6.JL27(IO,_CDR,_DIFF_RX_2C16N,_DQ13)

Not connected (* = marked no-connect by the designer): J1 144(RFU1)* 205(RFU2)* 227(RFU3)*; J2 144(RFU1)* 205(RFU2)* 227(RFU3)*; U6 JL29(IO,_DIFF_RX_2C17N,_DQ13)* JL31(IO,_CDR,_DIFF_RX_2C18N,_DQ13)* JL37(IO,_CDR,_DIFF_RX_2F15N,_DQ20)* JP28(IO,_DIFF_RX_2C17P,_DQ13)* JP30(IO,_RZQ_B_2C,_CDR,_DIFF_RX_2C18P,_DQ13)* JP36(IO,_CDR,_DIFF_RX_2F15P,_DQ20)* JY28(IO,_PLL_2C_B_CLKOUT1P,_PLL_2C_B_CLKOUT1,_PLL_2C_B_FB1,_DIFF_TX_2C17P,_DQS13)* JY30(IO,_CLK_B_2C_1N,_DIFF_TX_2C18N,_DQ13)* JY32(IO,_DIFF_TX_2F13N,_DQ20)* JY34(IO,_DIFF_TX_2F14P,_DQS20)* KC31(IO,_CLK_B_2C_1P,_DIFF_TX_2C18P,_DQ13)* KC35(IO,_DIFF_TX_2F14N,_DQSN20)* KF26(IO,_CLK_B_2C_0N,_CDR,_DIFF_RX_2C19N,_DQ14)* KF28(IO,_PLL_2C_B_CLKOUT0P,_PLL_2C_B_CLKOUT0,_PLL_2C_B_FB0,_DIFF_RX_2C20P,_DQ14)* KJ29(IO,_PLL_2C_B_CLKOUT0N,_DIFF_RX_2C20N,_DQ14)* KJ31(IO,_CDR,_DIFF_RX_2C21P,_DQ14)* KR27(IO,_DIFF_TX_2C19N,_DQ14)* KR31(IO,_DIFF_TX_2C21N,_DQ14)* KU26(IO,_DIFF_TX_2C19P,_DQ14)* KU28(IO,_DIFF_TX_2C20P,_DQS14)* KU30(IO,_DIFF_TX_2C21P,_DQ14)*; U12 6(NC0)* 9(NC1)*; U13 4(IOVL3)* 5(IOVL4)* 6(NC0)* 9(NC1)* 10(IOVCC4)* 11(IOVCC3)*

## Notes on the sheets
sheet 17
- DDR4/T DIMM CH0  INTERFACE -- FPGA SIDE 2C
sheet 18
- DDR4/T DIMM CH0  INTERFACE -- FPGA SIDE 2F
sheet 19
- DDR4/DDRT DIMM A
- x72bit DIMM Only
- DDR4 DIMM IF
- I2C Addr: 0xA0
- Put caps on VDD pins which are close to DIMM A/C pins
sheet 20
- DDR4/DDRT DIMM B
- x72bit DIMM Only
- DDR4 DIMM IF
- I2C Addr: 0xA1
- Put caps on VDD pins which are close to DIMM A/C pins
